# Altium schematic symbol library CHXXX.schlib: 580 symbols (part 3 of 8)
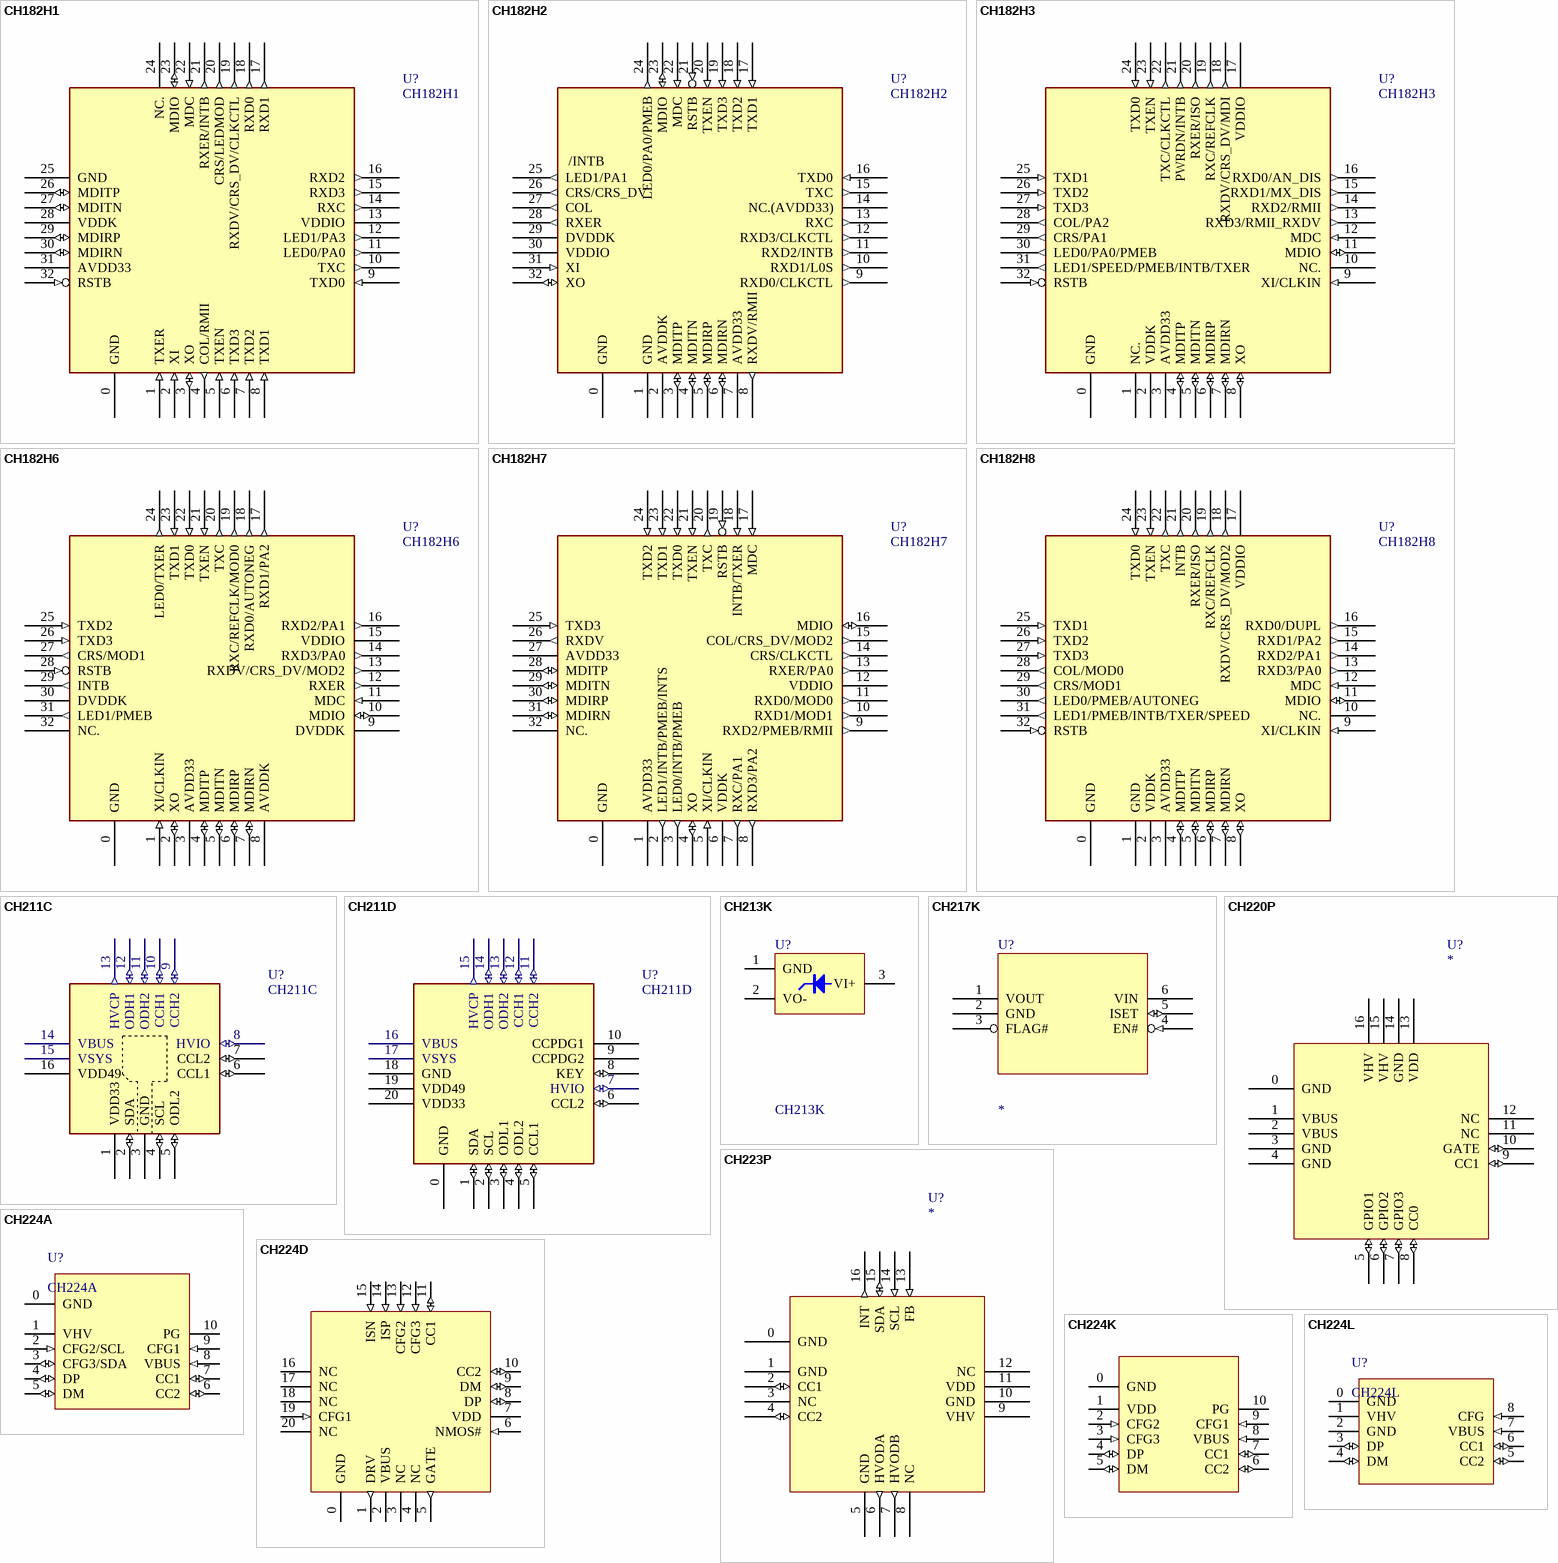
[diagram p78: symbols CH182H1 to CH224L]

## CH182H6
designator U?
MII/RMII 10/100M Ethernet PHY (Transceiver) with auto MDIX
footprint QFN32_5X5
pins: 0 GND (power), 1 XI/CLKIN (in), 2 XO (io), 3 AVDD33 (power), 4 MDITP (io), 5 MDITN (io), 6 MDIRP (io), 7 MDIRN (io), 8 AVDDK (power), 9 DVDDK (power), 10 MDIO (io), 11 MDC (in), 12 RXER (out), 13 RXDV/CRS_DV/MOD2 (out), 14 RXD3/PA0 (out), 15 VDDIO (power), 16 RXD2/PA1 (out), 17 RXD1/PA2 (out), 18 RXD0/AUTONEG (out), 19 RXC/REFCLK/MOD0 (out), 20 TXC (out), 21 TXEN (in), 22 TXD0 (in), 23 TXD1 (in), 24 LED0/TXER (out), 25 TXD2 (in), 26 TXD3 (in), 27 CRS/MOD1 (out), 28 RSTB (in), 29 INTB (out), 30 DVDDK (power), 31 LED1/PMEB (out), 32 NC.

## CH182H7
designator U?
MII/RMII 10/100M Ethernet PHY (Transceiver) with auto MDIX
footprint QFN32_5X5
pins: 0 GND (power), 1 AVDD33 (power), 2 LED1/INTB/PMEB/INTS (out), 3 LED0/INTB/PMEB (out), 4 XO (io), 5 XI/CLKIN (in), 6 VDDK (power), 7 RXC/PA1 (out), 8 RXD3/PA2 (out), 9 RXD2/PMEB/RMII (out), 10 RXD1/MOD1 (out), 11 RXD0/MOD0 (out), 12 VDDIO (power), 13 RXER/PA0 (out), 14 CRS/CLKCTL (out), 15 COL/CRS_DV/MOD2 (out), 16 MDIO (io), 17 MDC (in), 18 INTB/TXER (in), 19 RSTB (in), 20 TXC (out), 21 TXEN (in), 22 TXD0 (in), 23 TXD1 (in), 24 TXD2 (in), 25 TXD3 (in), 26 RXDV (out), 27 AVDD33 (power), 28 MDITP (io), 29 MDITN (io), 30 MDIRP (io), 31 MDIRN (io), 32 NC.

## CH182H8
designator U?
MII/RMII 10/100M Ethernet PHY (Transceiver) with auto MDIX
footprint QFN32_5X5
pins: 0 GND (power), 1 GND (power), 2 VDDK (power), 3 AVDD33 (power), 4 MDITP (io), 5 MDITN (io), 6 MDIRP (io), 7 MDIRN (io), 8 XO (io), 9 XI/CLKIN (in), 10 NC., 11 MDIO (io), 12 MDC (in), 13 RXD3/PA0 (out), 14 RXD2/PA1 (out), 15 RXD1/PA2 (out), 16 RXD0/DUPL (out), 17 VDDIO (power), 18 RXDV/CRS_DV/MOD2 (out), 19 RXC/REFCLK (out), 20 RXER/ISO (out), 21 INTB (out), 22 TXC (out), 23 TXEN (in), 24 TXD0 (in), 25 TXD1 (in), 26 TXD2 (in), 27 TXD3 (in), 28 COL/MOD0 (out), 29 CRS/MOD1 (out), 30 LED0/PMEB/AUTONEG (out), 31 LED1/PMEB/INTB/TXER/SPEED (out), 32 RSTB (in)

## CH211C
designator U?
28V USB PD & Type-C high voltage interface
footprint QFN16C_2X2
pins: 1 VDD33 (power), 2 SDA (io), 3 GND (power), 4 SCL (io), 5 ODL2 (io), 6 CCL1 (io), 7 CCL2 (io), 8 HVIO (io), 9 CCH2 (io), 10 CCH1 (io), 11 ODH2 (io), 12 ODH1 (io), 13 HVCP (out), 14 VBUS (power), 15 VSYS (power), 16 VDD49 (power)

## CH211D
designator U?
28V USB PD & Type-C high voltage interface
footprint QFN20_3X3
pins: 0 GND (power), 1 SDA (io), 2 SCL (io), 3 ODL1 (io), 4 ODL2 (io), 5 CCL1 (io), 6 CCL2 (io), 7 HVIO (io), 8 KEY (io), 9 CCPDG2 (power), 10 CCPDG1 (power), 11 CCH2 (io), 12 CCH1 (io), 13 ODH2 (io), 14 ODH1 (io), 15 HVCP (out), 16 VBUS (power), 17 VSYS (power), 18 GND (power), 19 VDD49 (power), 20 VDD33 (power)

## CH213K
designator U?
Ideal Diode 5V*1A
footprint SOT23L (Footprint not found)
footprint SOT-23-3
pins: 1 GND (power), 2 VO- (power), 3 VI+ (power)

## CH217K
designator U?
Current-Limited USB Power Distribution Switch
footprint SOT-23-6
pins: 1 VOUT (power), 2 GND (power), 3 FLAG# (oc), 4 EN# (in), 5 ISET (io), 6 VIN (power)

## CH220P
designator U?
USB PD & Type-C Power Manager
footprint QFN16_3X3
pins: 0 GND (power), 1 VBUS (power), 2 VBUS (power), 3 GND (power), 4 GND (power), 5 GPIO1 (io), 6 GPIO2 (io), 7 GPIO3 (io), 8 CC0 (io), 9 CC1 (io), 10 GATE (io), 11 NC, 12 NC, 13 VDD (power), 14 GND (power), 15 VHV (power), 16 VHV (power)

## CH223P
designator U?
USB PD & Type-C Power Provider Controller
footprint QFN16_3X3
pins: 0 GND (power), 1 GND, 2 CC1 (io), 3 NC (power), 4 CC2 (io), 5 GND (power), 6 HVODA (out), 7 HVODB (out), 8 NC, 9 VHV (power), 10 GND (power), 11 VDD (power), 12 NC, 13 FB (in), 14 SCL (in), 15 SDA (io), 16 INT (out)

## CH224A
designator U?
USB PD & Type-C & Fast Charge Power Consumer Controller
footprint ESSOP10
pins: 0 GND (power), 1 VHV (power), 2 CFG2/SCL (in), 3 CFG3/SDA (io), 4 DP (io), 5 DM (io), 6 CC2 (io), 7 CC1 (io), 8 VBUS (in), 9 CFG1 (in), 10 PG

## CH224D
designator U?  (value not drawn)
USB PD & Type-C & Fast Charge Power Consumer Controller
footprint QFN20_3X3
pins: 0 GND (power), 1 DRV (out), 2 VBUS (power), 3 NC, 4 NC, 5 GATE (out), 6 NMOS# (in), 7 VDD (power), 8 DP (io), 9 DM (io), 10 CC2 (io), 11 CC1 (io), 12 CFG3 (in), 13 CFG2 (in), 14 ISP (in), 15 ISN (in), 16 NC, 17 NC, 18 NC, 19 CFG1 (in), 20 NC

## CH224K
designator U?  (value not drawn)
USB PD & Type-C & Fast Charge Power Consumer Controller
footprint ESSOP10
pins: 0 GND (power), 1 VDD (power), 2 CFG2 (in), 3 CFG3 (in), 4 DP (io), 5 DM (io), 6 CC2 (io), 7 CC1 (io), 8 VBUS (in), 9 CFG1 (in), 10 PG

## CH224L
designator U?
USB PD & Type-C & Fast Charge Power Consumer Controller
footprint DFN8_2x2
pins: 0 GND (power), 1 VHV (power), 2 GND (power), 3 DP (io), 4 DM (io), 5 CC2 (io), 6 CC1 (io), 7 VBUS (in), 8 CFG (in)

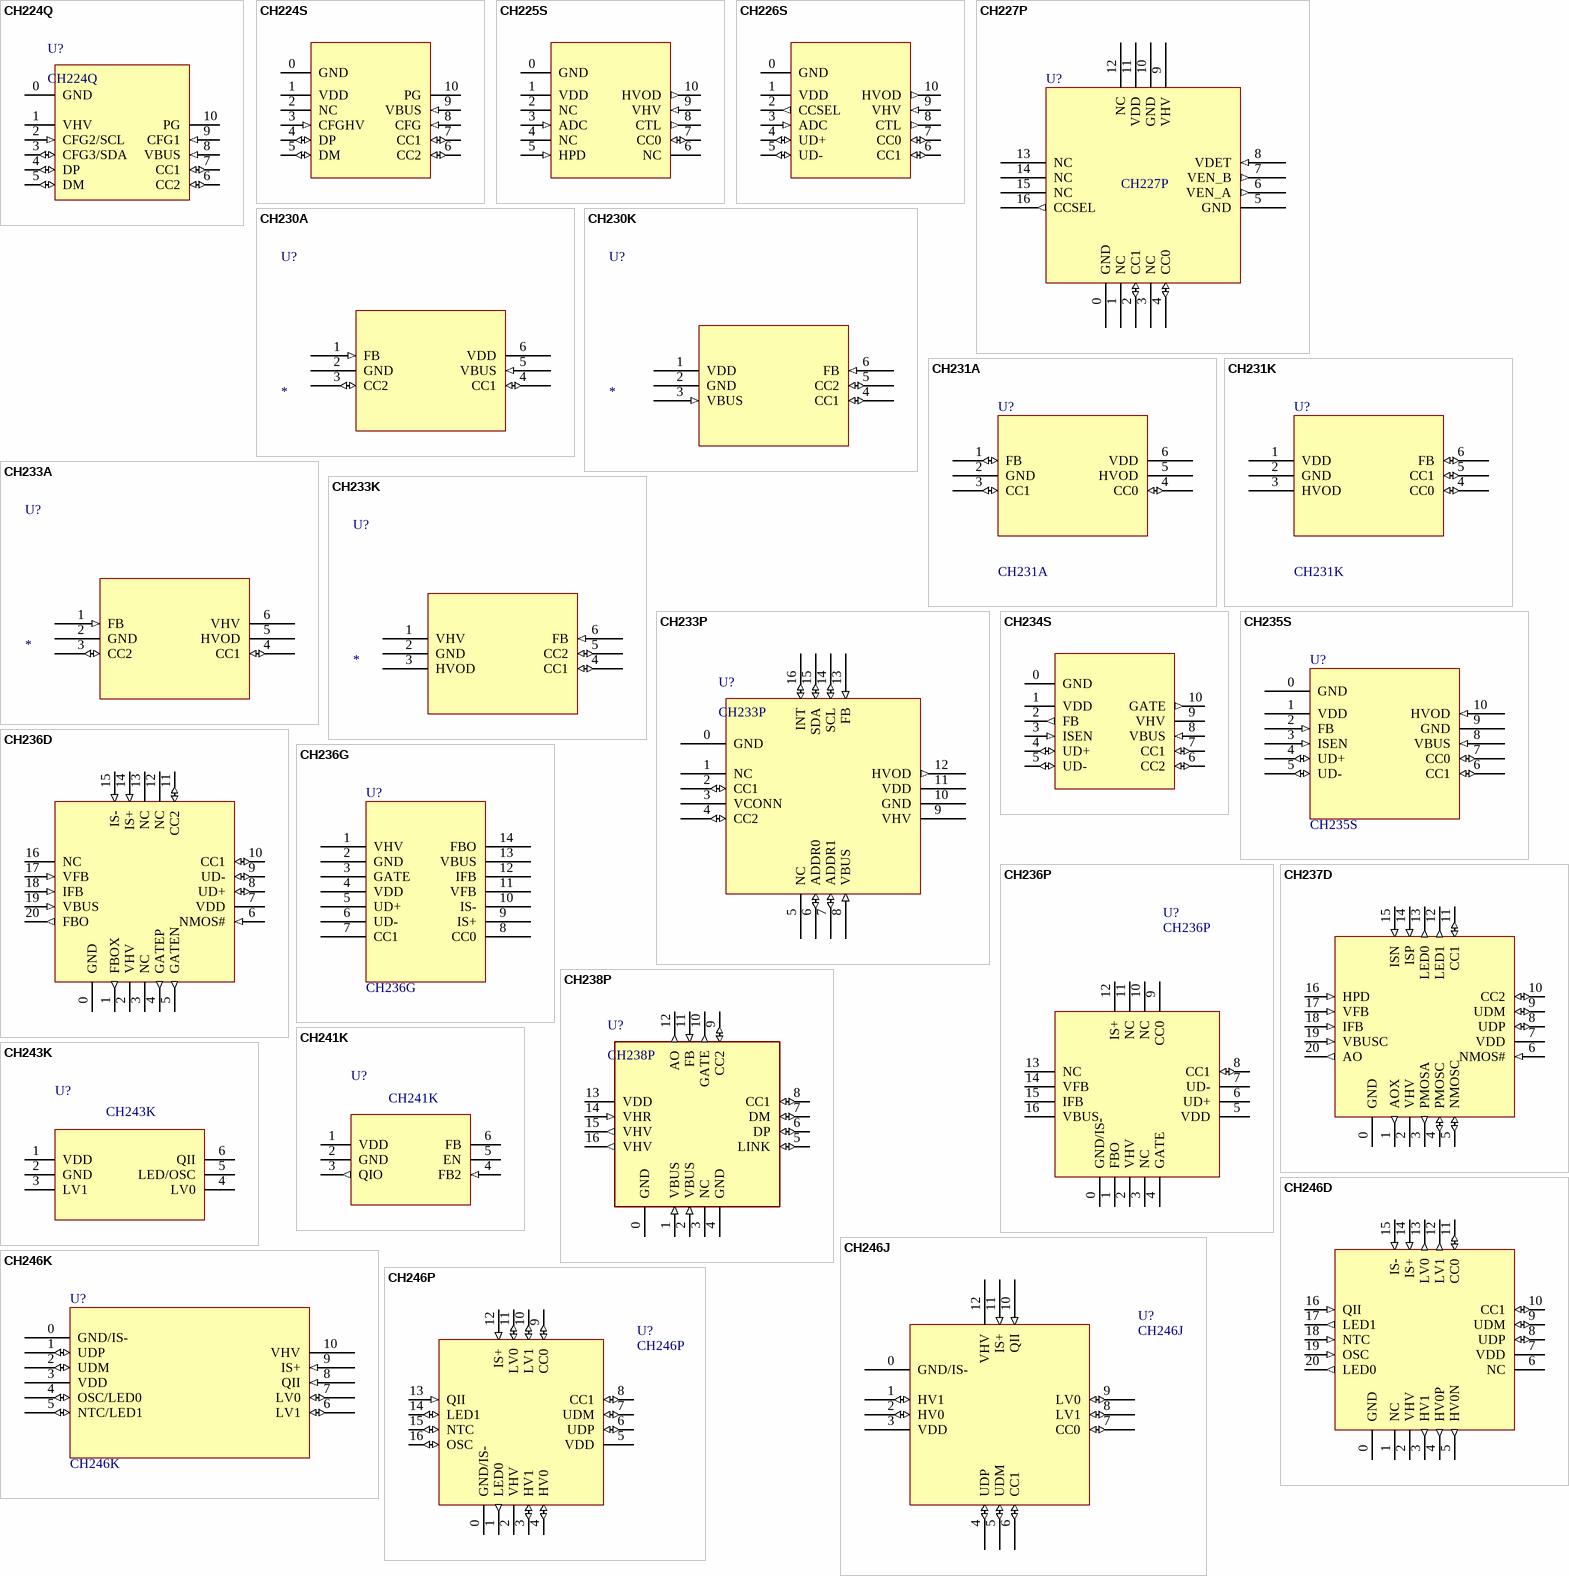
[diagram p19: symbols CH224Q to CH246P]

## CH224Q
designator U?
USB PD & Type-C & Fast Charge Power Consumer Controller
footprint DFN10_2X2 (Footprint not found)
pins: 0 GND (power), 1 VHV (power), 2 CFG2/SCL (in), 3 CFG3/SDA (io), 4 DP (io), 5 DM (io), 6 CC2 (io), 7 CC1 (io), 8 VBUS (in), 9 CFG1 (in), 10 PG

## CH224S
designator U?  (value not drawn)
USB PD & Type-C & Fast Charge Power Consumer Controller
footprint ESSOP10
pins: 0 GND (power), 1 VDD (power), 2 NC, 3 CFGHV (in), 4 DP (io), 5 DM (io), 6 CC2 (io), 7 CC1 (io), 8 CFG (in), 9 VBUS (in), 10 PG

## CH225S
designator U?  (value not drawn)
USB PD & Type-C & Fast Charge Power Consumer Controller
footprint ESSOP10
pins: 0 GND (power), 1 VDD (power), 2 NC, 3 ADC (in), 4 NC, 5 HPD (in), 6 NC, 7 CC0 (io), 8 CTL (out), 9 VHV (in), 10 HVOD (out)

## CH226S
designator U?  (value not drawn)
USB PD & Type-C & Fast Charge Power Consumer Controller
footprint ESSOP10
pins: 0 GND (power), 1 VDD (power), 2 CCSEL (out), 3 ADC (in), 4 UD+ (io), 5 UD- (io), 6 CC1 (io), 7 CC0 (io), 8 CTL (out), 9 VHV (in), 10 HVOD (out)

## CH227P
designator U?
USB PD & Type-C & Fast Charge Power Consumer Controller
footprint QFN16_3X3
pins: 0 GND (power), 1 NC, 2 CC1 (io), 3 NC, 4 CC0 (io), 5 GND (power), 6 VEN_A (out), 7 VEN_B (out), 8 VDET (in), 9 VHV (power), 10 GND (power), 11 VDD (power), 12 NC, 13 NC, 14 NC, 15 NC, 16 CCSEL (out)

## CH230A
designator U?
USB PD & Type-C Power Provider Controller
footprint SOT-23-6
pins: 1 FB (in), 2 GND (power), 3 CC2 (io), 4 CC1 (io), 5 VBUS (in), 6 VDD (power)

## CH230K
designator U?
USB PD & Type-C Power Provider Controller
footprint SOT-23-6
pins: 1 VDD (power), 2 GND (power), 3 VBUS (in), 4 CC1 (io), 5 CC2 (io), 6 FB (in)

## CH231A
designator U?
USB PD & Type-C Power Provider Controller
footprint SOT-23-6
pins: 1 FB (io), 2 GND (power), 3 CC1 (io), 4 CC0 (io), 5 HVOD (oc), 6 VDD (power)

## CH231K
designator U?
USB PD & Type-C Power Provider Controller
footprint SOT-23-6
pins: 1 VDD (power), 2 GND (power), 3 HVOD (oc), 4 CC0 (io), 5 CC1 (io), 6 FB (io)

## CH233A
designator U?
USB PD & Type-C Power Provider Controller
footprint SOT-23-6
pins: 1 FB (in), 2 GND (power), 3 CC2 (io), 4 CC1 (io), 5 HVOD (oc), 6 VHV (power)

## CH233K
designator U?
USB PD & Type-C Power Provider Controller
footprint SOT-23-6
pins: 1 VHV (power), 2 GND (power), 3 HVOD (oc), 4 CC1 (io), 5 CC2 (io), 6 FB (in)

## CH233P
designator U?
USB PD & Type-C Power Provider Controller
footprint QFN16_3X3
pins: 0 GND (power), 1 NC, 2 CC1 (io), 3 VCONN (power), 4 CC2 (io), 5 NC, 6 ADDR0 (io), 7 ADDR1 (io), 8 VBUS (in), 9 VHV (power), 10 GND (power), 11 VDD (power), 12 HVOD (out), 13 FB (in), 14 SCL (io), 15 SDA (io), 16 INT (io)

## CH234S
designator U?  (value not drawn)
USB PD & Type-C & Fast Charge Power Provider Controller
footprint ESSOP10
pins: 0 GND (power), 1 VDD (power), 2 FB (out), 3 ISEN (in), 4 UD+ (io), 5 UD- (io), 6 CC2 (io), 7 CC1 (io), 8 VBUS (in), 9 VHV (power), 10 GATE (out)

## CH235S
designator U?
USB PD & Type-C & Fast Charge Power Provider Controller
footprint ESSOP10
pins: 0 GND (power), 1 VDD (power), 2 FB (in), 3 ISEN (in), 4 UD+ (io), 5 UD- (io), 6 CC1 (io), 7 CC0 (io), 8 VBUS (in), 9 GND (power), 10 HVOD (in)

## CH236D
designator U?  (value not drawn)
USB PD & Type-C & Fast Charge Power Provider Controller
footprint QFN20_3X3
pins: 0 GND (power), 1 FBOX (out), 2 VHV (power), 3 NC, 4 GATEP (out), 5 GATEN (out), 6 NMOS# (in), 7 VDD (power), 8 UD+ (io), 9 UD- (io), 10 CC1 (io), 11 CC2 (io), 12 NC, 13 NC, 14 IS+ (in), 15 IS- (in), 16 NC, 17 VFB (in), 18 IFB (in), 19 VBUS (in), 20 FBO (out)

## CH236G
designator U?
USB PD & Type-C & Fast Charge Power Provider Controller
footprint SOP14
pins: 1 VHV, 2 GND (power), 3 GATE, 4 VDD (power), 5 UD+, 6 UD-, 7 CC1, 8 CC0 (power), 9 IS+, 10 IS- (power), 11 VFB, 12 IFB, 13 VBUS, 14 FBO (power)

## CH236P
designator U?
USB PD & Type-C & Fast Charge Power Provider Controller
footprint QFN16_3X3
pins: 0 GND/IS- (power), 1 FBO, 2 VHV (power), 3 NC, 4 GATE, 5 VDD (power), 6 UD+, 7 UD-, 8 CC1 (io), 9 CC0, 10 NC, 11 NC, 12 IS+, 13 NC, 14 VFB, 15 IFB, 16 VBUS

## CH237D
designator U?  (value not drawn)
USB PD & Type-C & Fast Charge Power Provider Controller, A+C
footprint QFN20_3X3
pins: 0 GND (power), 1 AOX (out), 2 VHV (power), 3 PMOSA (out), 4 PMOSC (io), 5 NMOSC (io), 6 NMOS# (in), 7 VDD (power), 8 UDP (io), 9 UDM (io), 10 CC2 (io), 11 CC1 (io), 12 LED1 (out), 13 LED0 (out), 14 ISP (in), 15 ISN (in), 16 HPD (in), 17 VFB (in), 18 IFB (in), 19 VBUSC (in), 20 AO (out)

## CH238P
designator U?
USB PD & Type-C & Fast Charge Power Provider Controller
footprint QFN16_3X3
pins: 0 GND, 1 VBUS (in), 2 VBUS (in), 3 NC, 4 GND, 5 LINK (io), 6 DP (io), 7 DM (io), 8 CC1 (io), 9 CC2 (io), 10 GATE (out), 11 FB (in), 12 AO (out), 13 VDD, 14 VHR (in), 15 VHV (out), 16 VHV (out)

## CH241K
designator U?
5W wireless power receiver IC
footprint SOT-23-6
pins: 1 VDD (power), 2 GND (power), 3 QIO (out), 4 FB2 (in), 5 EN (power), 6 FB

## CH243K
designator U?
5W wireless power transmitter IC
footprint SOT-23-6
pins: 1 VDD (power), 2 GND (power), 3 LV1, 4 LV0, 5 LED/OSC (power), 6 QII

## CH246D
designator U?  (value not drawn)
Wireless Charge Power Provider Controller with USB PD & Fast Charge Sink
footprint QFN20_3X3
pins: 0 GND (power), 1 NC, 2 VHV (power), 3 HV1 (out), 4 HV0P (out), 5 HV0N (out), 6 NC, 7 VDD (power), 8 UDP (io), 9 UDM (io), 10 CC1 (io), 11 CC0 (io), 12 LV1 (out), 13 LV0 (out), 14 IS+ (in), 15 IS- (in), 16 QII (in), 17 LED1 (out), 18 NTC (in), 19 OSC (in), 20 LED0 (out)

## CH246J
designator U?
Wireless Charge Power Provider Controller with USB PD & Fast Charge Sink
footprint QFN12_2X2
pins: 0 GND/IS- (power), 1 HV1 (io), 2 HV0 (io), 3 VDD (power), 4 UDP (io), 5 UDM (io), 6 CC1 (io), 7 CC0 (io), 8 LV1 (io), 9 LV0 (io), 10 QII (in), 11 IS+ (in), 12 VHV (power)

## CH246K
designator U?
Wireless Charge Power with X-drive
footprint ESSOP10
pins: 0 GND/IS- (power), 1 UDP (io), 2 UDM (io), 3 VDD (power), 4 OSC/LED0 (io), 5 NTC/LED1 (io), 6 LV1 (io), 7 LV0 (io), 8 QII (in), 9 IS+ (in), 10 VHV (power)

## CH246P
designator U?
Wireless Charge Power Provider Controller with USB PD & Fast Charge Sink
footprint QFN16_3X3
pins: 0 GND/IS- (power), 1 LED0 (out), 2 VHV (power), 3 HV1 (io), 4 HV0 (io), 5 VDD (power), 6 UDP (io), 7 UDM (io), 8 CC1 (io), 9 CC0 (io), 10 LV1 (io), 11 LV0 (io), 12 IS+ (in), 13 QII (in), 14 LED1 (io), 15 NTC (io), 16 OSC (io)

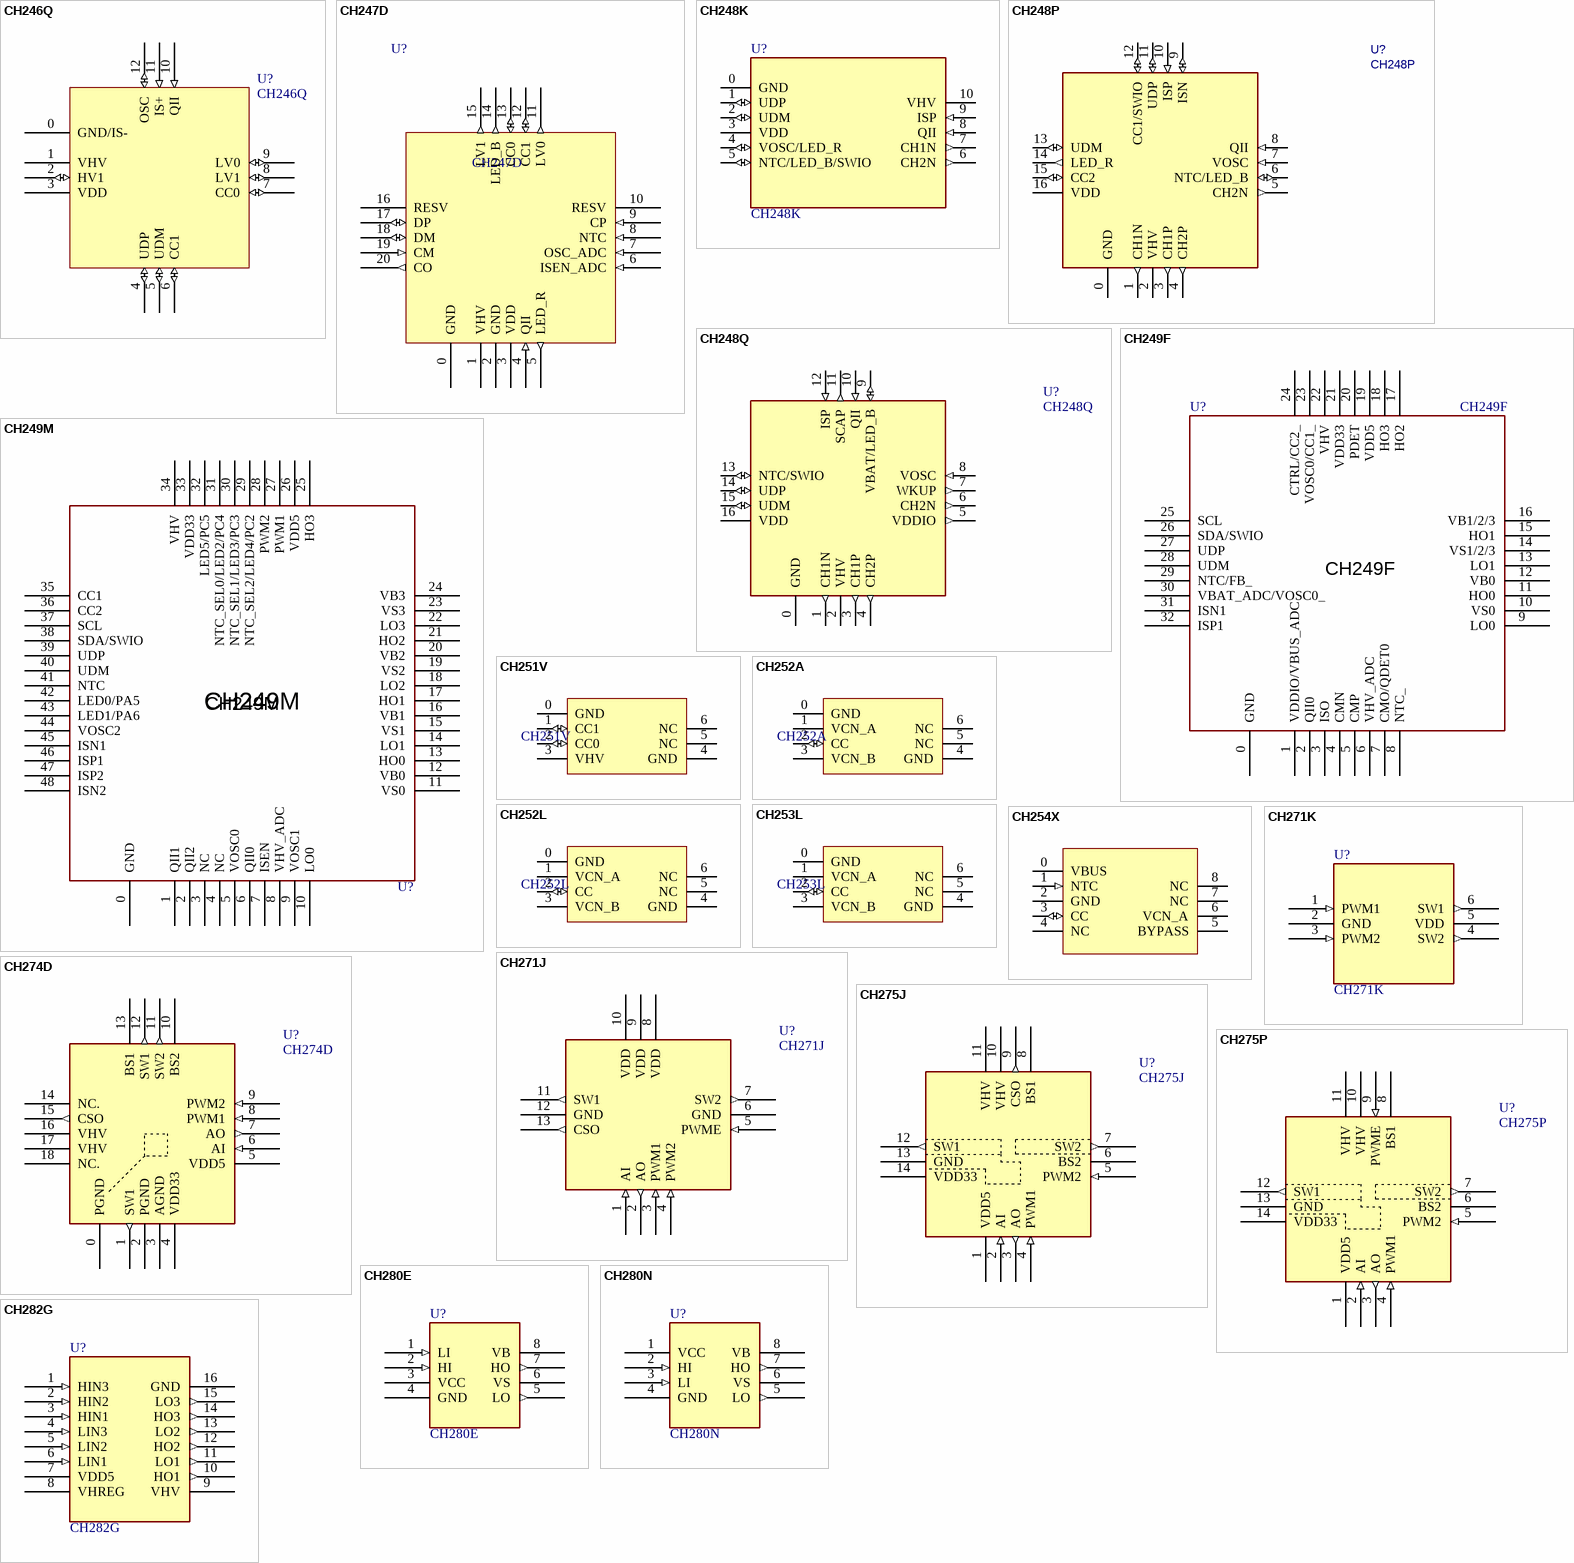
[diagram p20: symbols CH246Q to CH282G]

## CH246Q
designator U?
Wireless Charge Power with X-drive & PD Charge
footprint QFN12_2X2
pins: 0 GND/IS- (power), 1 VHV (power), 2 HV1 (io), 3 VDD (power), 4 UDP (io), 5 UDM (io), 6 CC1 (io), 7 CC0 (io), 8 LV1 (io), 9 LV0 (io), 10 QII (in), 11 IS+ (in), 12 OSC (io)

## CH247D
designator U?
Wireless Charge Power Provider Controller with USB PD & Fast Charge Sink
footprint QFN20_3X3
pins: 0 GND (power), 1 VHV (power), 2 GND (power), 3 VDD (power), 4 QII (in), 5 LED_R (out), 6 ISEN_ADC (in), 7 OSC_ADC (in), 8 NTC (in), 9 CP (in), 10 RESV, 11 LV0 (out), 12 CC1 (io), 13 CC0 (io), 14 LED_B (out), 15 LV1 (out), 16 RESV, 17 DP (io), 18 DM (io), 19 CM (in), 20 CO (out)

## CH248K
designator U?
RISC-V MCU with PD/ADC/UART/OA, for wireless charging
footprint ESSOP10
pins: 0 GND (power), 1 UDP (io), 2 UDM (io), 3 VDD (power), 4 VOSC/LED_R (io), 5 NTC/LED_B/SWIO (io), 6 CH2N (out), 7 CH1N (out), 8 QII (in), 9 ISP (in), 10 VHV (power)

## CH248P
designator U?
RISC-V MCU with PD/ADC/UART/OA, for wireless charging
footprint QFN16_3X3
pins: 0 GND (power), 1 CH1N (out), 2 VHV (power), 3 CH1P (out), 4 CH2P (out), 5 CH2N (out), 6 NTC/LED_B (io), 7 VOSC (in), 8 QII (in), 9 ISN (io), 10 ISP (in), 11 UDP (io), 12 CC1/SWIO (io), 13 UDM (io), 14 LED_R (out), 15 CC2 (io), 16 VDD (power)

## CH248Q
designator U?
RISC-V MCU with ADC/UART/OA
footprint QFN16_3X3
pins: 0 GND (power), 1 CH1N (out), 2 VHV (power), 3 CH1P (out), 4 CH2P (out), 5 VDDIO (out), 6 CH2N (out), 7 WKUP (out), 8 VOSC (in), 9 VBAT/LED_B (io), 10 QII (in), 11 SCAP (out), 12 ISP (in), 13 NTC/SWIO (io), 14 UDP (io), 15 UDM (io), 16 VDD (power)

## CH249F
designator U?
Wireless charging transmitter, supporting MPP, EPP, BPP, earphones, smartwatches, and other devices.
footprint QFN32_4X4
pins: 0 GND (power), 1 VDDIO/VBUS_ADC, 2 QII0, 3 ISO, 4 CMN, 5 CMP, 6 VHV_ADC, 7 CMO/QDET0, 8 NTC_, 9 LO0, 10 VS0, 11 HO0, 12 VB0, 13 LO1, 14 VS1/2/3, 15 HO1, 16 VB1/2/3, 17 HO2, 18 HO3, 19 VDD5 (power), 20 PDET, 21 VDD33 (power), 22 VHV (power), 23 VOSC0/CC1_, 24 CTRL/CC2_, 25 SCL, 26 SDA/SWIO, 27 UDP, 28 UDM, 29 NTC/FB_, 30 VBAT_ADC/VOSC0_, 31 ISN1, 32 ISP1

## CH249M
designator U?
Wireless charging transmitter, supporting EPP, BPP, earphones, smartwatches, and other devices£¬supporting three-way simultaneous charging.
footprint QFN48_5X5
pins: 0 GND (power), 1 QII1 (hiz), 2 QII2, 3 NC (hiz), 4 NC (hiz), 5 VOSC0 (hiz), 6 QII0 (hiz), 7 ISEN (hiz), 8 VHV_ADC (hiz), 9 VOSC1 (hiz), 10 LO0 (hiz), 11 VS0 (hiz), 12 VB0 (hiz), 13 HO0 (hiz), 14 LO1 (hiz), 15 VS1 (hiz), 16 VB1 (hiz), 17 HO1 (hiz), 18 LO2 (hiz), 19 VS2, 20 VB2 (hiz), 21 HO2 (hiz), 22 LO3 (hiz), 23 VS3 (hiz), 24 VB3 (hiz), 25 HO3 (hiz), 26 VDD5 (power), 27 PWM1 (hiz), 28 PWM2 (hiz), 29 NTC_SEL2/LED4/PC2 (hiz), 30 NTC_SEL1/LED3/PC3 (hiz), 31 NTC_SEL0/LED2/PC4 (hiz), 32 LED5/PC5 (oc), 33 VDD33 (hiz), 34 VHV (power), 35 CC1 (hiz), 36 CC2 (hiz), 37 SCL, 38 SDA/SWIO (hiz), 39 UDP, 40 UDM, 41 NTC, 42 LED0/PA5 (hiz), 43 LED1/PA6, 44 VOSC2, 45 ISN1 (hiz), 46 ISP1 (hiz), 47 ISP2 (hiz), 48 ISN2 (hiz)

## CH251V
designator U?
USB Type-C cable E-Marker
footprint DFN6_2X2
pins: 0 GND (power), 1 CC1 (io), 2 CC0 (io), 3 VHV (power), 4 GND (power), 5 NC, 6 NC

## CH252A
designator U?
USB Type-C cable E-Marker
footprint DFN6_2X2
pins: 0 GND (power), 1 VCN_A (power), 2 CC (io), 3 VCN_B (power), 4 GND (power), 5 NC, 6 NC

## CH252L
designator U?
USB Type-C cable E-Marker
footprint DFN6_2X2
pins: 0 GND (power), 1 VCN_A (power), 2 CC (io), 3 VCN_B (power), 4 GND (power), 5 NC, 6 NC

## CH253L
designator U?
USB Type-C cable E-Marker
footprint DFN6_2X2
pins: 0 GND (power), 1 VCN_A (power), 2 CC (io), 3 VCN_B (power), 4 GND (power), 5 NC, 6 NC

## CH254X
designator U?  (value not drawn)
USB Type-C cable E-Marker with over temperature protection
footprint DFN8_2x2 (Footprint not found)
pins: 0 VBUS (power), 1 NTC (in), 2 GND (power), 3 CC (io), 4 NC, 5 BYPASS (power), 6 VCN_A (power), 7 NC, 8 NC

## CH271J
designator U?
5V Full-Bridge Power Stage for Wireless Power Transmitter
footprint QFN13F_2X2 (Footprint not found)
pins: 1 AI (in), 2 AO (out), 3 PWM1 (in), 4 PWM2 (in), 5 PWME (in), 6 GND (power), 7 SW2 (out), 8 VDD (power), 9 VDD (power), 10 VDD (power), 11 SW1 (out), 12 GND (power), 13 CSO (out)

## CH271K
designator U?
5V Full-Bridge Power Stage
footprint SOT-23-6
pins: 1 PWM1 (in), 2 GND (power), 3 PWM2 (in), 4 SW2 (out), 5 VDD (power), 6 SW1 (out)

## CH274D
designator U?
12V Full-Bridge Power Stage for Wireless Power Transmitter
footprint QFN18E_3X3
pins: 0 PGND (power), 1 SW1 (out), 2 PGND (power), 3 AGND (power), 4 VDD33 (power), 5 VDD5 (power), 6 AI (in), 7 AO (out), 8 PWM1 (in), 9 PWM2 (in), 10 BS2 (power), 11 SW2 (out), 12 SW1 (out), 13 BS1 (power), 14 NC., 15 CSO (out), 16 VHV (power), 17 VHV (power), 18 NC.

## CH275J
designator U?
20V Full-Bridge Power Stage for Wireless Power Transmitter
footprint QFN14F_3X3 (Footprint not found)
pins: 1 VDD5 (power), 2 AI (in), 3 AO (out), 4 PWM1 (in), 5 PWM2 (in), 6 BS2 (power), 7 SW2 (out), 8 BS1 (power), 9 CSO (out), 10 VHV (power), 11 VHV (power), 12 SW1 (out), 13 GND (power), 14 VDD33 (power)

## CH275P
designator U?
20V Full-Bridge Power Stage for Wireless Power Transmitter
footprint QFN14F_3X3 (Footprint not found)
pins: 1 VDD5 (power), 2 AI (in), 3 AO (out), 4 PWM1 (in), 5 PWM2 (in), 6 BS2 (power), 7 SW2 (out), 8 BS1 (power), 9 PWME (in), 10 VHV (power), 11 VHV (power), 12 SW1 (out), 13 GND (power), 14 VDD33 (power)

## CH280E
designator U?
NMOS half-bridge gate driver
footprint SOP8
pins: 1 LI (in), 2 HI (in), 3 VCC (power), 4 GND (power), 5 LO (out), 6 VS (power), 7 HO (out), 8 VB (power)

## CH280N
designator U?
NMOS half-bridge gate driver
footprint SOP8
pins: 1 VCC (power), 2 HI (in), 3 LI (in), 4 GND (power), 5 LO (out), 6 VS (power), 7 HO (out), 8 VB (power)

## CH282G
designator U?
three-phase P/NMOS gate driver with LDO
footprint SOP16
pins: 1 HIN3 (in), 2 HIN2 (in), 3 HIN1 (in), 4 LIN3 (in), 5 LIN2 (in), 6 LIN1 (in), 7 VDD5 (power), 8 VHREG (power), 9 VHV (power), 10 HO1 (out), 11 LO1 (out), 12 HO2 (out), 13 LO2 (out), 14 HO3 (out), 15 LO3 (out), 16 GND (power)

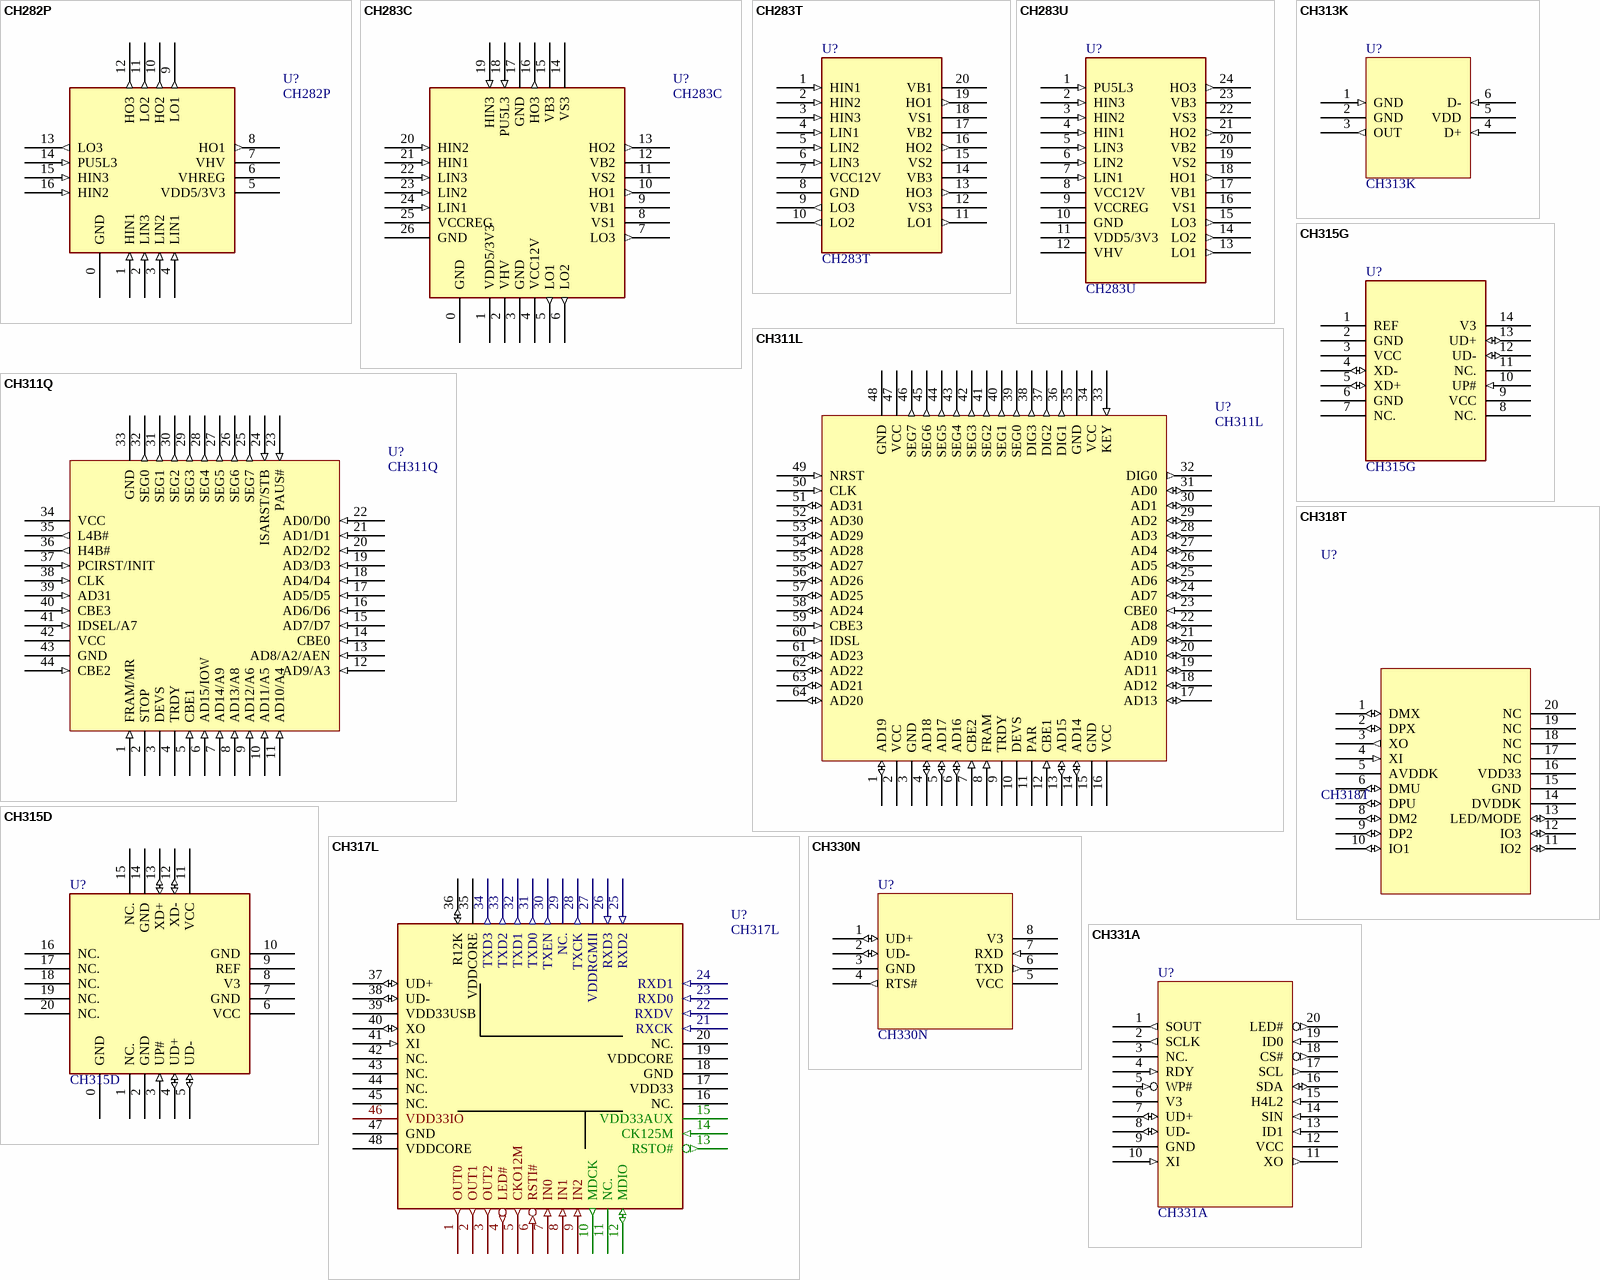
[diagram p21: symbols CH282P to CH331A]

## CH282P
designator U?
three-phase P/NMOS gate driver with LDO
footprint QFN16_3X3
pins: 0 GND (power), 1 HIN1 (in), 2 LIN3 (in), 3 LIN2 (in), 4 LIN1 (in), 5 VDD5/3V3 (power), 6 VHREG (power), 7 VHV (power), 8 HO1 (out), 9 LO1 (out), 10 HO2 (out), 11 LO2 (out), 12 HO3 (out), 13 LO3 (out), 14 PU5L3 (in), 15 HIN3 (in), 16 HIN2 (in)

## CH283C
designator U?
three-phase NMOS gate driver with LDO
footprint QFN26C_3X3
pins: 0 GND (power), 1 VDD5/3V3 (power), 2 VHV (power), 3 GND (power), 4 VCC12V (power), 5 LO1 (out), 6 LO2 (out), 7 LO3 (out), 8 VS1 (power), 9 VB1 (power), 10 HO1 (out), 11 VS2 (power), 12 VB2 (power), 13 HO2 (out), 14 VS3 (power), 15 VB3 (power), 16 HO3 (out), 17 GND (power), 18 PU5L3 (in), 19 HIN3 (in), 20 HIN2 (in), 21 HIN1 (in), 22 LIN3 (in), 23 LIN2 (in), 24 LIN1 (in), 25 VCCREG (power), 26 GND (power)

## CH283T
designator U?
three-phase NMOS gate driver
footprint TSSOP20
pins: 1 HIN1 (in), 2 HIN2 (in), 3 HIN3 (in), 4 LIN1 (in), 5 LIN2 (in), 6 LIN3 (in), 7 VCC12V (power), 8 GND (power), 9 LO3 (out), 10 LO2 (out), 11 LO1 (out), 12 VS3 (power), 13 HO3 (out), 14 VB3 (power), 15 VS2 (power), 16 HO2 (out), 17 VB2 (power), 18 VS1 (power), 19 HO1 (out), 20 VB1 (power)

## CH283U
designator U?
three-phase NMOS gate driver with LDO
footprint QSOP24
pins: 1 PU5L3 (in), 2 HIN3 (in), 3 HIN2 (in), 4 HIN1 (in), 5 LIN3 (in), 6 LIN2 (in), 7 LIN1 (in), 8 VCC12V (power), 9 VCCREG (power), 10 GND (power), 11 VDD5/3V3 (power), 12 VHV (power), 13 LO1 (out), 14 LO2 (out), 15 LO3 (out), 16 VS1 (power), 17 VB1 (power), 18 HO1 (out), 19 VS2 (power), 20 VB2 (power), 21 HO2 (out), 22 VS3 (power), 23 VB3 (power), 24 HO3 (out)

## CH311L
designator U?
PC debug port monitor, 4 Digits * 8 Segments, PCI
footprint LQFP64
pins: 1 AD19 (io), 2 VCC (power), 3 GND (power), 4 AD18 (io), 5 AD17 (io), 6 AD16 (io), 7 CBE2 (in), 8 FRAM (in), 9 TRDY (hiz), 10 DEVS (hiz), 11 PAR (hiz), 12 CBE1 (in), 13 AD15 (io), 14 AD14 (io), 15 GND (power), 16 VCC (power), 17 AD13 (io), 18 AD12 (io), 19 AD11 (io), 20 AD10 (io), 21 AD9 (io), 22 AD8 (io), 23 CBE0 (in), 24 AD7 (io), 25 AD6 (io), 26 AD5 (io), 27 AD4 (io), 28 AD3 (io), 29 AD2 (io), 30 AD1 (io), 31 AD0 (io), 32 DIG0 (out), 33 KEY (in), 34 VCC (power), 35 GND (power), 36 DIG1 (out), 37 DIG2 (out), 38 DIG3 (out), 39 SEG0 (out), 40 SEG1 (out), 41 SEG2 (out), 42 SEG3 (out), 43 SEG4 (out), 44 SEG5 (out), 45 SEG6 (out), 46 SEG7 (out), 47 VCC (power), 48 GND (power), 49 NRST (in), 50 CLK (in), 51 AD31 (io), 52 AD30 (io), 53 AD29 (io), 54 AD28 (io), 55 AD27 (io), 56 AD26 (io), 57 AD25 (io), 58 AD24 (io), 59 CBE3 (in), 60 IDSL (in), 61 AD23 (io), 62 AD22 (io), 63 AD21 (io), 64 AD20 (io)

## CH311Q
designator U?
PC debug port monitor, 2 Digits * 8 Segments, PCI & ISA & LPT
footprint LQFP44
pins: 1 FRAM/MR (in), 2 STOP (hiz), 3 DEVS (hiz), 4 TRDY (hiz), 5 CBE1 (in), 6 AD15/IOW (in), 7 AD14/A9 (in), 8 AD13/A8 (in), 9 AD12/A6 (in), 10 AD11/A5 (in), 11 AD10/A4 (in), 12 AD9/A3 (in), 13 AD8/A2/AEN (in), 14 CBE0 (in), 15 AD7/D7 (in), 16 AD6/D6 (in), 17 AD5/D5 (in), 18 AD4/D4 (in), 19 AD3/D3 (in), 20 AD2/D2 (in), 21 AD1/D1 (in), 22 AD0/D0 (in), 23 PAUS# (in), 24 ISARST/STB (in), 25 SEG7 (out), 26 SEG6 (out), 27 SEG5 (out), 28 SEG4 (out), 29 SEG3 (out), 30 SEG2 (out), 31 SEG1 (out), 32 SEG0 (out), 33 GND (power), 34 VCC (power), 35 L4B# (out), 36 H4B# (out), 37 PCIRST/INIT (in), 38 CLK (in), 39 AD31 (in), 40 CBE3 (in), 41 IDSEL/A7 (in), 42 VCC (power), 43 GND (power), 44 CBE2 (in)

## CH313K
designator U?
USB transfer detection
footprint SOT-363
pins: 1 GND (in), 2 GND (power), 3 OUT (out), 4 D+ (in), 5 VDD (power), 6 D- (in)

## CH315D
designator U?
USB lengthen wire controller, Full-Speed & Low-Speed
footprint QFN20_3X3 (Footprint not found)
pins: 0 GND (power), 1 NC., 2 GND (power), 3 UP# (in), 4 UD+ (io), 5 UD- (io), 6 VCC (power), 7 GND (power), 8 V3 (power), 9 REF (power), 10 GND (power), 11 VCC (power), 12 XD- (io), 13 XD+ (io), 14 GND (power), 15 NC., 16 NC., 17 NC., 18 NC., 19 NC., 20 NC.

## CH315G
designator U?
USB lengthen wire controller, Full-Speed & Low-Speed
footprint SOP14
pins: 1 REF (power), 2 GND (power), 3 VCC (power), 4 XD- (io), 5 XD+ (io), 6 GND (power), 7 NC., 8 NC., 9 VCC (power), 10 UP# (in), 11 NC., 12 UD- (io), 13 UD+ (io), 14 V3 (power)

## CH317L
designator U?
High-Speed USB lengthen wire controller for longer distance
footprint LQFP48
pins: 1 OUT0 (out), 2 OUT1 (out), 3 OUT2 (out), 4 LED# (out), 5 CKO12M (out), 6 RSTI# (in), 7 IN0 (in), 8 IN1 (in), 9 IN2 (in), 10 MDCK (out), 11 NC., 12 MDIO (io), 13 RSTO# (out), 14 CK125M (in), 15 VDD33AUX (power), 16 NC., 17 VDD33 (power), 18 GND (power), 19 VDDCORE (power), 20 NC., 21 RXCK (in), 22 RXDV (in), 23 RXD0 (in), 24 RXD1 (in), 25 RXD2 (in), 26 RXD3 (in), 27 VDDRGMII (power), 28 TXCK (out), 29 NC., 30 TXEN (out), 31 TXD0 (out), 32 TXD1 (out), 33 TXD2 (out), 34 TXD3 (out), 35 VDDCORE (power), 36 R12K (io), 37 UD+ (io), 38 UD- (io), 39 VDD33USB (power), 40 XO (io), 41 XI (in), 42 NC., 43 NC., 44 NC., 45 NC., 46 VDD33IO (power), 47 GND (power), 48 VDDCORE (power)

## CH318T
designator U?
2 ports High-Speed USB Hub Isolator
footprint TSSOP20
pins: 1 DMX (io), 2 DPX (io), 3 XO (out), 4 XI (in), 5 AVDDK (power), 6 DMU (io), 7 DPU (io), 8 DM2 (io), 9 DP2 (io), 10 IO1 (io), 11 IO2 (io), 12 IO3 (io), 13 LED/MODE (io), 14 DVDDK (power), 15 GND (power), 16 VDD33 (power), 17 NC, 18 NC, 19 NC, 20 NC

## CH330N
designator U?
USB to TTL Serial / UART
footprint SOP8
pins: 1 UD+ (io), 2 UD- (io), 3 GND (power), 4 RTS# (out), 5 VCC (power), 6 TXD (out), 7 RXD (in), 8 V3 (power)

## CH331A
designator U?
Mini USB Disk Controller for serial EEPROM or Flash
footprint SSOP20
pins: 1 SOUT (out), 2 SCLK (out), 3 NC., 4 RDY (in), 5 WP# (in), 6 V3 (power), 7 UD+ (io), 8 UD- (io), 9 GND (power), 10 XI (in), 11 XO (out), 12 VCC (power), 13 ID1 (in), 14 SIN (in), 15 H4L2 (in), 16 SDA (io), 17 SCL (out), 18 CS# (out), 19 ID0 (in), 20 LED# (out)

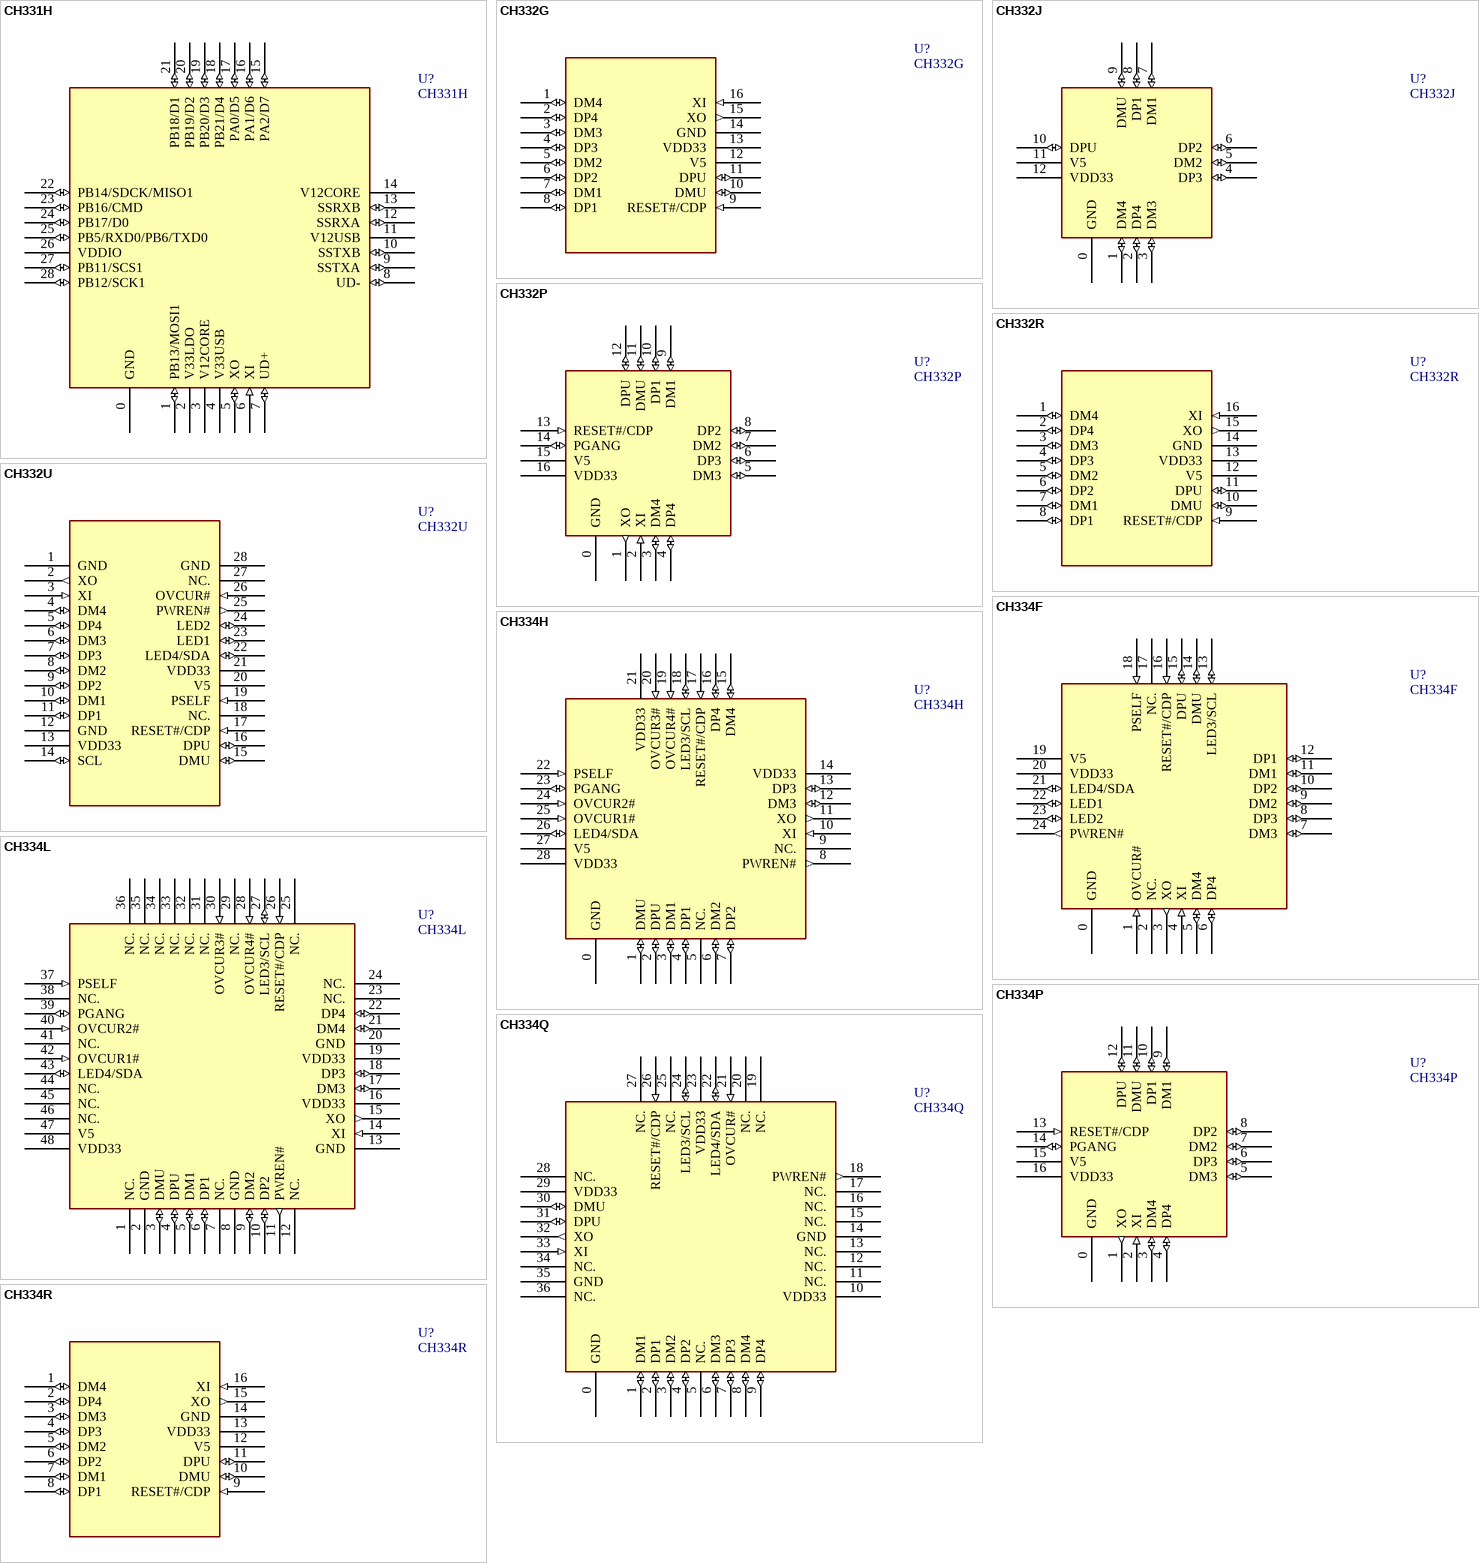
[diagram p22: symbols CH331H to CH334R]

## CH331H
designator U?
RISC-V USB 3.0 Disk Controller with AES/SM4
footprint QFN28_5X5
pins: 0 GND (power), 1 PB13/MOSI1 (io), 2 V33LDO (power), 3 V12CORE (power), 4 V33USB (power), 5 XO (io), 6 XI (in), 7 UD+ (io), 8 UD- (io), 9 SSTXA (io), 10 SSTXB (io), 11 V12USB (power), 12 SSRXA (io), 13 SSRXB (io), 14 V12CORE (power), 15 PA2/D7 (io), 16 PA1/D6 (io), 17 PA0/D5 (io), 18 PB21/D4 (io), 19 PB20/D3 (io), 20 PB19/D2 (io), 21 PB18/D1 (io), 22 PB14/SDCK/MISO1 (io), 23 PB16/CMD (io), 24 PB17/D0 (io), 25 PB5/RXD0/PB6/TXD0 (io), 26 VDDIO (power), 27 PB11/SCS1 (io), 28 PB12/SCK1 (io)

## CH332G
designator U?
4 ports High-Speed USB STT Hub
footprint SOP16 (Footprint not found)
pins: 1 DM4 (io), 2 DP4 (io), 3 DM3 (io), 4 DP3 (io), 5 DM2 (io), 6 DP2 (io), 7 DM1 (io), 8 DP1 (io), 9 RESET#/CDP (in), 10 DMU (io), 11 DPU (io), 12 V5 (power), 13 VDD33 (power), 14 GND (power), 15 XO (out), 16 XI (in)

## CH332J
designator U?
4 ports High-Speed USB STT Hub with internal oscillator
footprint QFN12_2X2
pins: 0 GND (power), 1 DM4 (io), 2 DP4 (io), 3 DM3 (io), 4 DP3 (io), 5 DM2 (io), 6 DP2 (io), 7 DM1 (io), 8 DP1 (io), 9 DMU (io), 10 DPU (io), 11 V5 (power), 12 VDD33 (power)

## CH332P
designator U?
4 ports High-Speed USB STT Hub
footprint QFN16_3X3 (Footprint not found)
pins: 0 GND (power), 1 XO (out), 2 XI (in), 3 DM4 (io), 4 DP4 (io), 5 DM3 (io), 6 DP3 (io), 7 DM2 (io), 8 DP2 (io), 9 DM1 (io), 10 DP1 (io), 11 DMU (io), 12 DPU (io), 13 RESET#/CDP (in), 14 PGANG (io), 15 V5 (power), 16 VDD33 (power)

## CH332R
designator U?
4 ports High-Speed USB STT Hub
footprint QSOP16 (Footprint not found)
pins: 1 DM4 (io), 2 DP4 (io), 3 DM3 (io), 4 DP3 (io), 5 DM2 (io), 6 DP2 (io), 7 DM1 (io), 8 DP1 (io), 9 RESET#/CDP (in), 10 DMU (io), 11 DPU (io), 12 V5 (power), 13 VDD33 (power), 14 GND (power), 15 XO (out), 16 XI (in)

## CH332U
designator U?
4 ports High-Speed USB STT Hub with over current detect & power control
footprint QSOP28 (Footprint not found)
pins: 1 GND (power), 2 XO (out), 3 XI (in), 4 DM4 (io), 5 DP4 (io), 6 DM3 (io), 7 DP3 (io), 8 DM2 (io), 9 DP2 (io), 10 DM1 (io), 11 DP1 (io), 12 GND (power), 13 VDD33 (power), 14 SCL (io), 15 DMU (io), 16 DPU (io), 17 RESET#/CDP (in), 18 NC., 19 PSELF (in), 20 V5 (power), 21 VDD33 (power), 22 LED4/SDA (io), 23 LED1 (io), 24 LED2 (io), 25 PWREN# (out), 26 OVCUR# (in), 27 NC., 28 GND (power)

## CH334F
designator U?
4 ports High-Speed USB MTT Hub with over current detect & power control
footprint QFN24_4X4 (Footprint not found)
pins: 0 GND (power), 1 OVCUR# (in), 2 NC., 3 XO (out), 4 XI (in), 5 DM4 (io), 6 DP4 (io), 7 DM3 (io), 8 DP3 (io), 9 DM2 (io), 10 DP2 (io), 11 DM1 (io), 12 DP1 (io), 13 LED3/SCL (io), 14 DMU (io), 15 DPU (io), 16 RESET#/CDP (in), 17 NC., 18 PSELF (in), 19 V5 (power), 20 VDD33 (power), 21 LED4/SDA (io), 22 LED1 (io), 23 LED2 (io), 24 PWREN# (out)

## CH334H
designator U?
4 ports High-Speed USB MTT Hub with 4 over current detect
footprint QFN28_5X5 (Footprint not found)
pins: 0 GND (power), 1 DMU (io), 2 DPU (io), 3 DM1 (io), 4 DP1 (io), 5 NC., 6 DM2 (io), 7 DP2 (io), 8 PWREN# (out), 9 NC., 10 XI (in), 11 XO (out), 12 DM3 (io), 13 DP3 (io), 14 VDD33 (power), 15 DM4 (io), 16 DP4 (io), 17 RESET#/CDP (in), 18 LED3/SCL (io), 19 OVCUR4# (in), 20 OVCUR3# (in), 21 VDD33 (power), 22 PSELF (in), 23 PGANG (io), 24 OVCUR2# (in), 25 OVCUR1# (in), 26 LED4/SDA (io), 27 V5 (power), 28 VDD33 (power)

## CH334L
designator U?
4 ports High-Speed USB MTT Hub with 4 over current detect
footprint LQFP48 (Footprint not found)
pins: 1 NC., 2 GND (power), 3 DMU (io), 4 DPU (io), 5 DM1 (io), 6 DP1 (io), 7 NC., 8 GND (power), 9 DM2 (io), 10 DP2 (io), 11 PWREN# (out), 12 NC., 13 GND (power), 14 XI (in), 15 XO (out), 16 VDD33 (power), 17 DM3 (io), 18 DP3 (io), 19 VDD33 (power), 20 GND (power), 21 DM4 (io), 22 DP4 (io), 23 NC., 24 NC., 25 NC., 26 RESET#/CDP (in), 27 LED3/SCL (io), 28 OVCUR4# (in), 29 NC., 30 OVCUR3# (in), 31 NC., 32 NC., 33 NC., 34 NC., 35 NC., 36 NC., 37 PSELF (in), 38 NC., 39 PGANG (io), 40 OVCUR2# (in), 41 NC., 42 OVCUR1# (in), 43 LED4/SDA (io), 44 NC., 45 NC., 46 NC., 47 V5 (power), 48 VDD33 (power)

## CH334P
designator U?
4 ports High-Speed USB MTT Hub
footprint QFN16_3X3 (Footprint not found)
pins: 0 GND (power), 1 XO (out), 2 XI (in), 3 DM4 (io), 4 DP4 (io), 5 DM3 (io), 6 DP3 (io), 7 DM2 (io), 8 DP2 (io), 9 DM1 (io), 10 DP1 (io), 11 DMU (io), 12 DPU (io), 13 RESET#/CDP (in), 14 PGANG (io), 15 V5 (power), 16 VDD33 (power)

## CH334Q
designator U?
4 ports High-Speed USB MTT Hub with over current detect & power control
footprint QFN36_6X6
pins: 0 GND (power), 1 DM1 (io), 2 DP1 (io), 3 DM2 (io), 4 DP2 (io), 5 NC., 6 DM3 (io), 7 DP3 (io), 8 DM4 (io), 9 DP4 (io), 10 VDD33 (power), 11 NC., 12 NC., 13 NC., 14 GND (power), 15 NC., 16 NC., 17 NC., 18 PWREN# (out), 19 NC., 20 NC., 21 OVCUR# (in), 22 LED4/SDA (io), 23 VDD33 (power), 24 LED3/SCL (io), 25 NC., 26 RESET#/CDP (in), 27 NC., 28 NC., 29 VDD33 (power), 30 DMU (io), 31 DPU (io), 32 XO (out), 33 XI (in), 34 NC., 35 GND (power), 36 NC.

## CH334R
designator U?
4 ports High-Speed USB MTT Hub
footprint QSOP16 (Footprint not found)
pins: 1 DM4 (io), 2 DP4 (io), 3 DM3 (io), 4 DP3 (io), 5 DM2 (io), 6 DP2 (io), 7 DM1 (io), 8 DP1 (io), 9 RESET#/CDP (in), 10 DMU (io), 11 DPU (io), 12 V5 (power), 13 VDD33 (power), 14 GND (power), 15 XO (out), 16 XI (in)

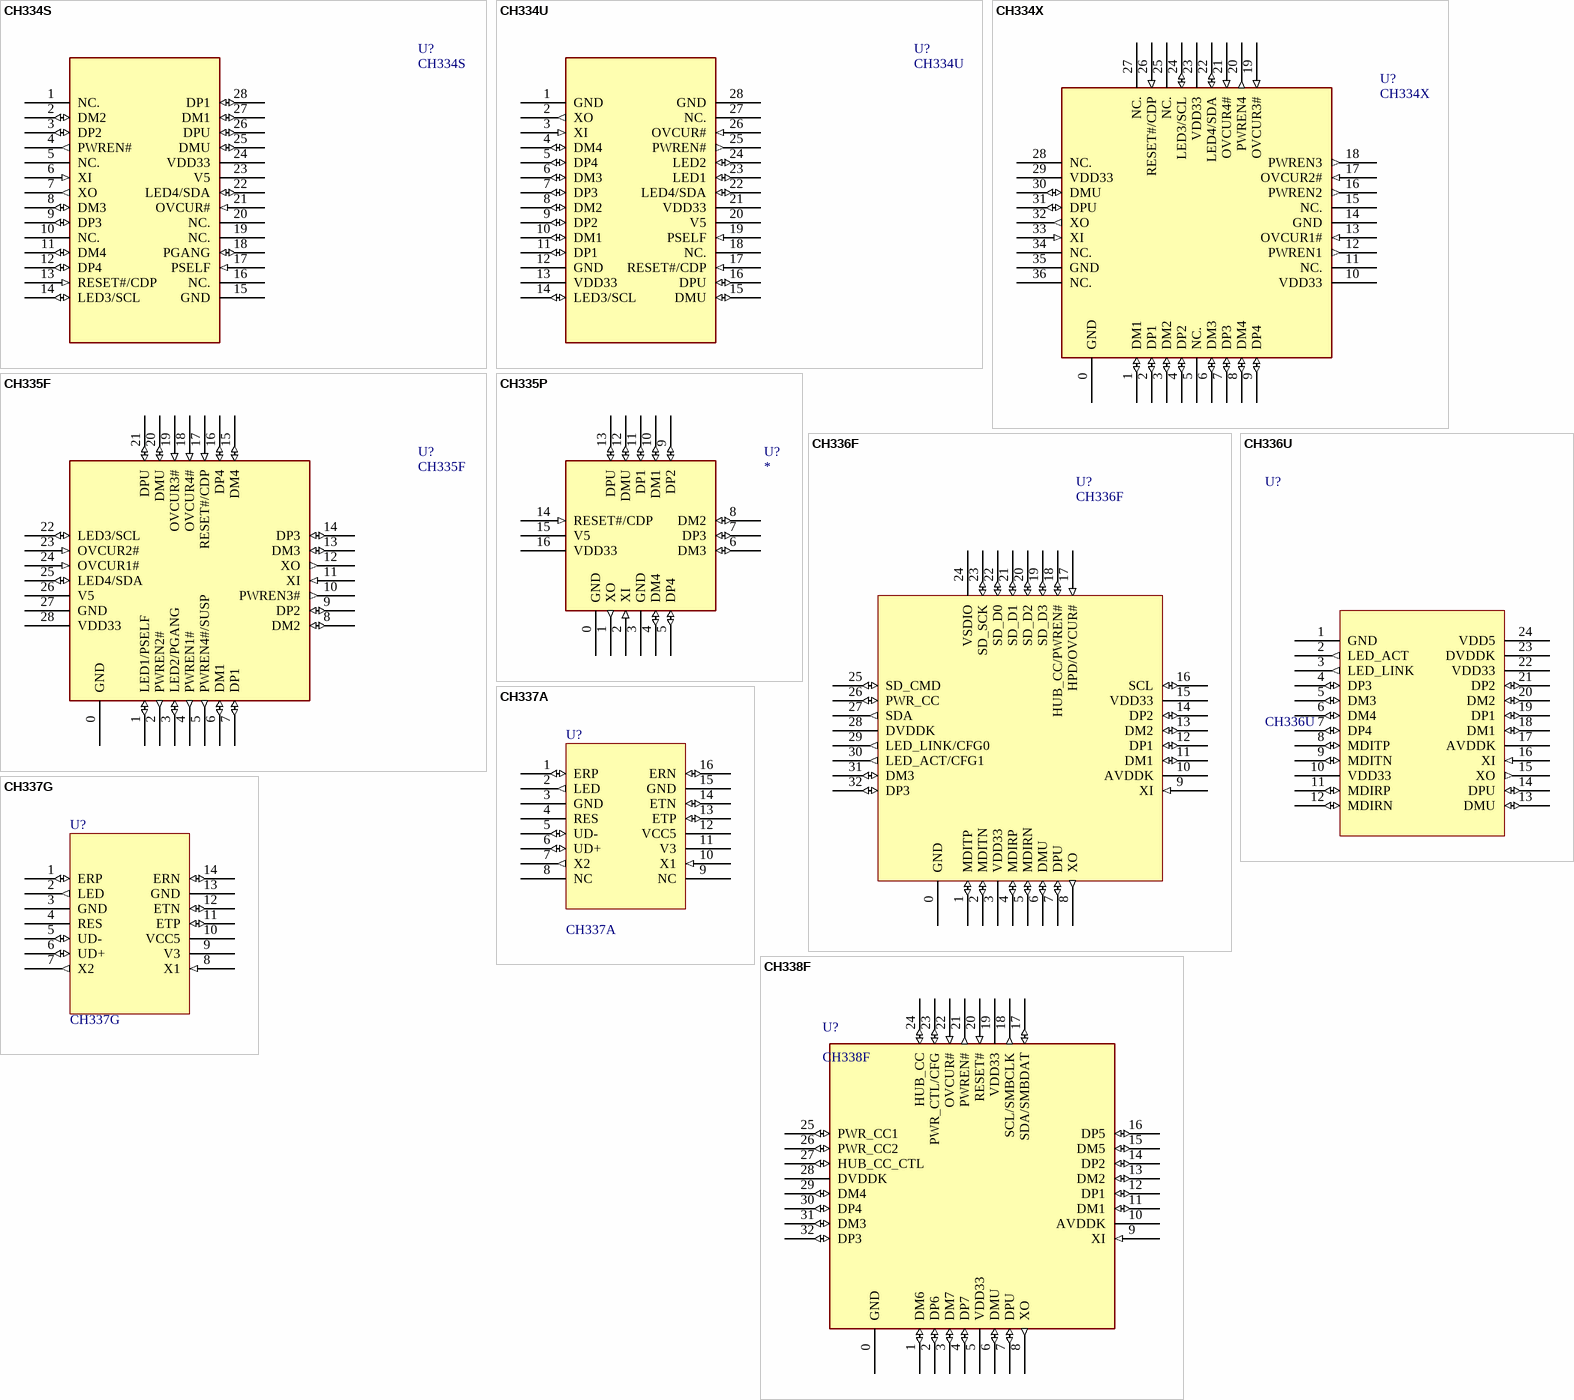
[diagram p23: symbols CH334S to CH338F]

## CH334S
designator U?
4 ports High-Speed USB MTT Hub with over current detect & power control
footprint SSOP28 (Footprint not found)
pins: 1 NC., 2 DM2 (io), 3 DP2 (io), 4 PWREN# (out), 5 NC., 6 XI (in), 7 XO (out), 8 DM3 (io), 9 DP3 (io), 10 NC., 11 DM4 (io), 12 DP4 (io), 13 RESET#/CDP (in), 14 LED3/SCL (io), 15 GND (power), 16 NC., 17 PSELF (in), 18 PGANG (io), 19 NC., 20 NC., 21 OVCUR# (in), 22 LED4/SDA (io), 23 V5 (power), 24 VDD33 (power), 25 DMU (io), 26 DPU (io), 27 DM1 (io), 28 DP1 (io)

## CH334U
designator U?
4 ports High-Speed USB MTT Hub with over current detect & power control
footprint QSOP28 (Footprint not found)
pins: 1 GND (power), 2 XO (out), 3 XI (in), 4 DM4 (io), 5 DP4 (io), 6 DM3 (io), 7 DP3 (io), 8 DM2 (io), 9 DP2 (io), 10 DM1 (io), 11 DP1 (io), 12 GND (power), 13 VDD33 (power), 14 LED3/SCL (io), 15 DMU (io), 16 DPU (io), 17 RESET#/CDP (in), 18 NC., 19 PSELF (in), 20 V5 (power), 21 VDD33 (power), 22 LED4/SDA (io), 23 LED1 (io), 24 LED2 (io), 25 PWREN# (out), 26 OVCUR# (in), 27 NC., 28 GND (power)

## CH334X
designator U?
4 ports High-Speed USB MTT Hub with 4 over current detect & power control
footprint QFN36_6X6
pins: 0 GND (power), 1 DM1 (io), 2 DP1 (io), 3 DM2 (io), 4 DP2 (io), 5 NC., 6 DM3 (io), 7 DP3 (io), 8 DM4 (io), 9 DP4 (io), 10 VDD33 (power), 11 NC., 12 PWREN1 (out), 13 OVCUR1# (in), 14 GND (power), 15 NC., 16 PWREN2 (out), 17 OVCUR2# (in), 18 PWREN3 (out), 19 OVCUR3# (in), 20 PWREN4 (out), 21 OVCUR4# (in), 22 LED4/SDA (io), 23 VDD33 (power), 24 LED3/SCL (io), 25 NC., 26 RESET#/CDP (in), 27 NC., 28 NC., 29 VDD33 (power), 30 DMU (io), 31 DPU (io), 32 XO (out), 33 XI (in), 34 NC., 35 GND (power), 36 NC.

## CH335F
designator U?
4 ports High-Speed USB MTT Hub with 4 over current detect & power control
footprint QFN28_4X4
pins: 0 GND (power), 1 LED1/PSELF (io), 2 PWREN2# (out), 3 LED2/PGANG (io), 4 PWREN1# (out), 5 PWREN4#/SUSP (out), 6 DM1 (io), 7 DP1 (io), 8 DM2 (io), 9 DP2 (io), 10 PWREN3# (out), 11 XI (in), 12 XO (out), 13 DM3 (io), 14 DP3 (io), 15 DM4 (io), 16 DP4 (io), 17 RESET#/CDP (in), 18 OVCUR4# (in), 19 OVCUR3# (in), 20 DMU (io), 21 DPU (io), 22 LED3/SCL (io), 23 OVCUR2# (in), 24 OVCUR1# (in), 25 LED4/SDA (io), 26 V5 (power), 27 GND (power), 28 VDD33 (power)

## CH335P
designator U?
4 ports High-Speed USB MTT Hub with internal oscillator
footprint QFN16C_2X2
pins: 0 GND (power), 1 XO (out), 2 XI (in), 3 GND (power), 4 DM4 (io), 5 DP4 (io), 6 DM3 (io), 7 DP3 (io), 8 DM2 (io), 9 DP2 (io), 10 DM1 (io), 11 DP1 (io), 12 DMU (io), 13 DPU (io), 14 RESET#/CDP (in), 15 V5 (power), 16 VDD33 (power)

## CH336F
designator U?
3 ports High-Speed USB MTT Hub with PD & SDIO & ethernet
footprint QFN32_4X4
pins: 0 GND (power), 1 MDITP (io), 2 MDITN (io), 3 VDD33 (power), 4 MDIRP (io), 5 MDIRN (io), 6 DMU (io), 7 DPU (io), 8 XO (out), 9 XI (in), 10 AVDDK (power), 11 DM1 (io), 12 DP1 (io), 13 DM2 (io), 14 DP2 (io), 15 VDD33 (power), 16 SCL (io), 17 HPD/OVCUR# (in), 18 HUB_CC/PWREN# (io), 19 SD_D3 (io), 20 SD_D2 (io), 21 SD_D1 (io), 22 SD_D0 (io), 23 SD_SCK (io), 24 VSDIO (power), 25 SD_CMD (io), 26 PWR_CC (io), 27 SDA (out), 28 DVDDK (power), 29 LED_LINK/CFG0 (out), 30 LED_ACT/CFG1 (out), 31 DM3 (io), 32 DP3 (io)

## CH336U
designator U?
4 ports High-Speed USB MTT Hub with ethernet
footprint QSOP24
pins: 1 GND (power), 2 LED_ACT (out), 3 LED_LINK (out), 4 DP3 (io), 5 DM3 (io), 6 DM4 (io), 7 DP4 (io), 8 MDITP (io), 9 MDITN (io), 10 VDD33 (power), 11 MDIRP (io), 12 MDIRN (io), 13 DMU (io), 14 DPU (io), 15 XO (out), 16 XI (in), 17 AVDDK (power), 18 DM1 (io), 19 DP1 (io), 20 DM2 (io), 21 DP2 (io), 22 VDD33 (power), 23 DVDDK (power), 24 VDD5 (power)

## CH337A
designator U?
USB to 10Mbps Ethernet
footprint SOP16
pins: 1 ERP (io), 2 LED (out), 3 GND (power), 4 RES, 5 UD- (io), 6 UD+ (io), 7 X2 (out), 8 NC, 9 NC, 10 X1 (in), 11 V3 (power), 12 VCC5 (power), 13 ETP (io), 14 ETN (io), 15 GND (power), 16 ERN (io)

## CH337G
designator U?
USB to 10Mbps Ethernet
footprint SOP14
pins: 1 ERP (io), 2 LED (out), 3 GND (power), 4 RES, 5 UD- (io), 6 UD+ (io), 7 X2 (out), 8 X1 (in), 9 V3 (power), 10 VCC5 (power), 11 ETP (io), 12 ETN (io), 13 GND (power), 14 ERN (io)

## CH338F
designator U?
7 ports High-Speed USB MTT Hub with PD
footprint QFN32_4X4
pins: 0 GND (power), 1 DM6 (io), 2 DP6 (io), 3 DM7 (io), 4 DP7 (io), 5 VDD33 (power), 6 DMU (io), 7 DPU (io), 8 XO (out), 9 XI (in), 10 AVDDK (power), 11 DM1 (io), 12 DP1 (io), 13 DM2 (io), 14 DP2 (io), 15 DM5 (io), 16 DP5 (io), 17 SDA/SMBDAT (io), 18 SCL/SMBCLK (out), 19 VDD33 (power), 20 RESET# (in), 21 PWREN# (out), 22 OVCUR# (in), 23 PWR_CTL/CFG (io), 24 HUB_CC (io), 25 PWR_CC1 (io), 26 PWR_CC2 (io), 27 HUB_CC_CTL (io), 28 DVDDK (power), 29 DM4 (io), 30 DP4 (io), 31 DM3 (io), 32 DP3 (io)

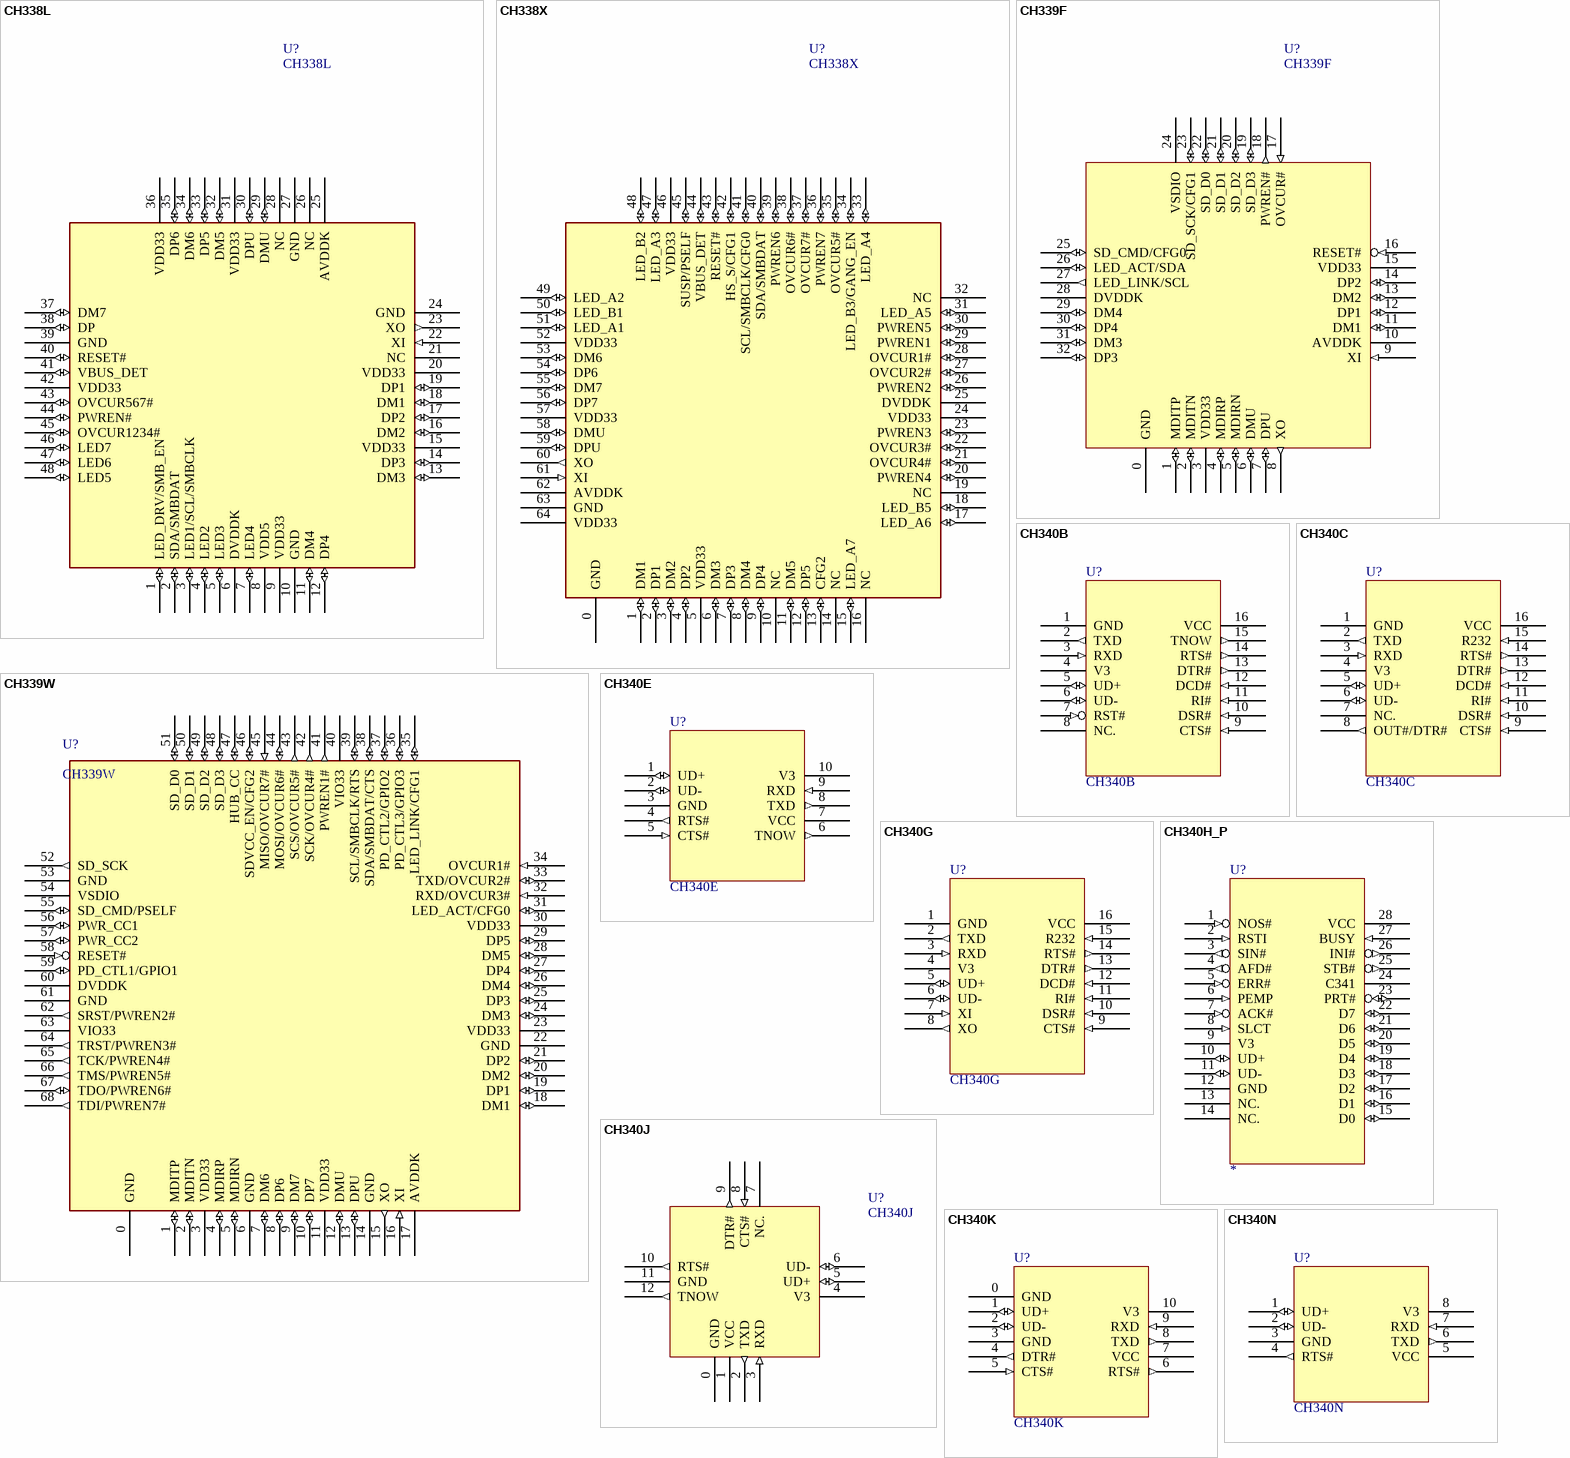
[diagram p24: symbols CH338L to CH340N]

## CH338L
designator U?
7 ports High-Speed USB MTT Hub
footprint LQFP48
pins: 1 LED_DRV/SMB_EN (io), 2 SDA/SMBDAT (io), 3 LED1/SCL/SMBCLK (io), 4 LED2 (io), 5 LED3 (io), 6 DVDDK (power), 7 LED4 (io), 8 VDD5 (power), 9 VDD33 (power), 10 GND (power), 11 DM4 (io), 12 DP4 (io), 13 DM3 (io), 14 DP3 (io), 15 VDD33 (power), 16 DM2 (io), 17 DP2 (io), 18 DM1 (io), 19 DP1 (io), 20 VDD33 (power), 21 NC, 22 XI (in), 23 XO (out), 24 GND (power), 25 AVDDK (power), 26 NC, 27 GND (power), 28 NC, 29 DMU (io), 30 DPU (io), 31 VDD33 (power), 32 DM5 (io), 33 DP5 (io), 34 DM6 (io), 35 DP6 (io), 36 VDD33 (power), 37 DM7 (io), 38 DP (io), 39 GND (power), 40 RESET# (io), 41 VBUS_DET (io), 42 VDD33 (power), 43 OVCUR567# (io), 44 PWREN# (io), 45 OVCUR1234# (io), 46 LED7 (io), 47 LED6 (io), 48 LED5 (io)

## CH338X
designator U?
7 ports High-Speed USB MTT Hub
footprint QFN64_9X9
pins: 0 GND (power), 1 DM1 (io), 2 DP1 (io), 3 DM2 (io), 4 DP2 (io), 5 VDD33 (power), 6 DM3 (io), 7 DP3 (io), 8 DM4 (io), 9 DP4 (io), 10 NC, 11 DM5 (io), 12 DP5 (io), 13 CFG2 (io), 14 NC, 15 LED_A7 (io), 16 NC, 17 LED_A6 (io), 18 LED_B5 (io), 19 NC, 20 PWREN4 (io), 21 OVCUR4# (io), 22 OVCUR3# (io), 23 PWREN3 (io), 24 VDD33 (power), 25 DVDDK (power), 26 PWREN2 (io), 27 OVCUR2# (io), 28 OVCUR1# (io), 29 PWREN1 (io), 30 PWREN5 (io), 31 LED_A5 (io), 32 NC, 33 LED_A4 (io), 34 LED_B3/GANG_EN (io), 35 OVCUR5# (io), 36 PWREN7 (io), 37 OVCUR7# (io), 38 OVCUR6# (io), 39 PWREN6 (io), 40 SDA/SMBDAT (io), 41 SCL/SMBCLK/CFG0 (io), 42 HS_S/CFG1 (io), 43 RESET# (io), 44 VBUS_DET (io), 45 SUSP/PSELF (io), 46 VDD33 (power), 47 LED_A3 (io), 48 LED_B2 (io), 49 LED_A2 (io), 50 LED_B1 (io), 51 LED_A1 (io), 52 VDD33 (power), 53 DM6 (io), 54 DP6 (io), 55 DM7 (io), 56 DP7 (io), 57 VDD33 (power), 58 DMU (io), 59 DPU (io), 60 XO (out), 61 XI (in), 62 AVDDK (power), 63 GND (power), 64 VDD33 (power)

## CH339F
designator U?
4 ports High-Speed USB MTT Hub with SDIO & ethernet
footprint QFN32_4X4
pins: 0 GND (power), 1 MDITP (io), 2 MDITN (io), 3 VDD33 (power), 4 MDIRP (io), 5 MDIRN (io), 6 DMU (io), 7 DPU (io), 8 XO (out), 9 XI (in), 10 AVDDK (power), 11 DM1 (io), 12 DP1 (io), 13 DM2 (io), 14 DP2 (io), 15 VDD33 (power), 16 RESET# (in), 17 OVCUR# (in), 18 PWREN# (out), 19 SD_D3 (io), 20 SD_D2 (io), 21 SD_D1 (io), 22 SD_D0 (io), 23 SD_SCK/CFG1 (io), 24 VSDIO (power), 25 SD_CMD/CFG0 (io), 26 LED_ACT/SDA (io), 27 LED_LINK/SCL (out), 28 DVDDK (power), 29 DM4 (io), 30 DP4 (io), 31 DM3 (io), 32 DP3 (io)

## CH339W
designator U?
7 ports High-Speed USB MTT Hub with PD & SDIO & ethernet
footprint QFN68_8X8
pins: 0 GND (power), 1 MDITP (io), 2 MDITN (io), 3 VDD33 (power), 4 MDIRP (io), 5 MDIRN (io), 6 GND (power), 7 DM6 (io), 8 DP6 (io), 9 DM7 (io), 10 DP7 (io), 11 VDD33 (power), 12 DMU (io), 13 DPU (io), 14 GND (power), 15 XO (out), 16 XI (in), 17 AVDDK (power), 18 DM1 (io), 19 DP1 (io), 20 DM2 (io), 21 DP2 (io), 22 GND (power), 23 VDD33 (power), 24 DM3 (io), 25 DP3 (io), 26 DM4 (io), 27 DP4 (io), 28 DM5 (io), 29 DP5 (io), 30 VDD33 (power), 31 LED_ACT/CFG0 (io), 32 RXD/OVCUR3# (in), 33 TXD/OVCUR2# (io), 34 OVCUR1# (in), 35 LED_LINK/CFG1 (io), 36 PD_CTL3/GPIO3 (io), 37 PD_CTL2/GPIO2 (io), 38 SDA/SMBDAT/CTS (io), 39 SCL/SMBCLK/RTS (io), 40 VIO33 (power), 41 PWREN1# (out), 42 SCK/OVCUR4# (out), 43 SCS/OVCUR5# (out), 44 MOSI/OVCUR6# (io), 45 MISO/OVCUR7# (in), 46 SDVCC_EN/CFG2 (io), 47 HUB_CC (io), 48 SD_D3 (io), 49 SD_D2 (io), 50 SD_D1 (io), 51 SD_D0 (io), 52 SD_SCK (out), 53 GND (power), 54 VSDIO (power), 55 SD_CMD/PSELF (io), 56 PWR_CC1 (io), 57 PWR_CC2 (io), 58 RESET# (in), 59 PD_CTL1/GPIO1 (io), 60 DVDDK (power), 61 GND (power), 62 SRST/PWREN2# (out), 63 VIO33 (power), 64 TRST/PWREN3# (out), 65 TCK/PWREN4# (out), 66 TMS/PWREN5# (out), 67 TDO/PWREN6# (io), 68 TDI/PWREN7# (out)

## CH340B
designator U?
USB to TTL Serial / UART, Integrated clock
footprint SOP16
pins: 1 GND (power), 2 TXD (out), 3 RXD (in), 4 V3 (power), 5 UD+ (io), 6 UD- (io), 7 RST# (in), 8 NC., 9 CTS# (in), 10 DSR# (in), 11 RI# (in), 12 DCD# (in), 13 DTR# (out), 14 RTS# (out), 15 TNOW (out), 16 VCC (power)

## CH340C
designator U?
USB to TTL Serial / UART
footprint SOP16
pins: 1 GND (power), 2 TXD (out), 3 RXD (in), 4 V3 (power), 5 UD+ (io), 6 UD- (io), 7 NC., 8 OUT#/DTR# (out), 9 CTS# (in), 10 DSR# (in), 11 RI# (in), 12 DCD# (in), 13 DTR# (out), 14 RTS# (out), 15 R232 (in), 16 VCC (power)

## CH340E
designator U?
USB to TTL Serial / UART
footprint MSOP10
pins: 1 UD+ (io), 2 UD- (io), 3 GND (power), 4 RTS# (out), 5 CTS# (in), 6 TNOW (out), 7 VCC (power), 8 TXD (out), 9 RXD (in), 10 V3 (power)

## CH340G
designator U?
USB to TTL Serial / UART
footprint SOP16
pins: 1 GND (power), 2 TXD (out), 3 RXD (in), 4 V3 (power), 5 UD+ (io), 6 UD- (io), 7 XI (in), 8 XO (out), 9 CTS# (in), 10 DSR# (in), 11 RI# (in), 12 DCD# (in), 13 DTR# (out), 14 RTS# (out), 15 R232 (in), 16 VCC (power)

## CH340H_P
designator U?
USB to Print Port / Parallel
footprint SOP28
footprint DIP28
pins: 1 NOS# (in), 2 RSTI (in), 3 SIN# (out), 4 AFD# (out), 5 ERR# (in), 6 PEMP (in), 7 ACK# (in), 8 SLCT (in), 9 V3 (power), 10 UD+ (io), 11 UD- (io), 12 GND (power), 13 NC., 14 NC., 15 D0 (io), 16 D1 (io), 17 D2 (io), 18 D3 (io), 19 D4 (io), 20 D5 (io), 21 D6 (io), 22 D7 (io), 23 PRT# (io), 24 C341, 25 STB# (out), 26 INI# (out), 27 BUSY (in), 28 VCC (power)

## CH340J
designator U?
USB to TTL Serial / UART
footprint QFN12_2X2
pins: 0 GND (power), 1 VCC (power), 2 TXD (out), 3 RXD (in), 4 V3 (power), 5 UD+ (io), 6 UD- (io), 7 NC., 8 CTS# (in), 9 DTR# (out), 10 RTS# (out), 11 GND (power), 12 TNOW (out)

## CH340K
designator U?
USB to TTL Serial / UART for dual power
footprint ESSOP10
pins: 0 GND (power), 1 UD+ (io), 2 UD- (io), 3 GND (power), 4 DTR# (out), 5 CTS# (in), 6 RTS# (out), 7 VCC (power), 8 TXD (out), 9 RXD (in), 10 V3 (power)

## CH340N
designator U?
USB to TTL Serial / UART
footprint SOP8
pins: 1 UD+ (io), 2 UD- (io), 3 GND (power), 4 RTS# (out), 5 VCC (power), 6 TXD (out), 7 RXD (in), 8 V3 (power)

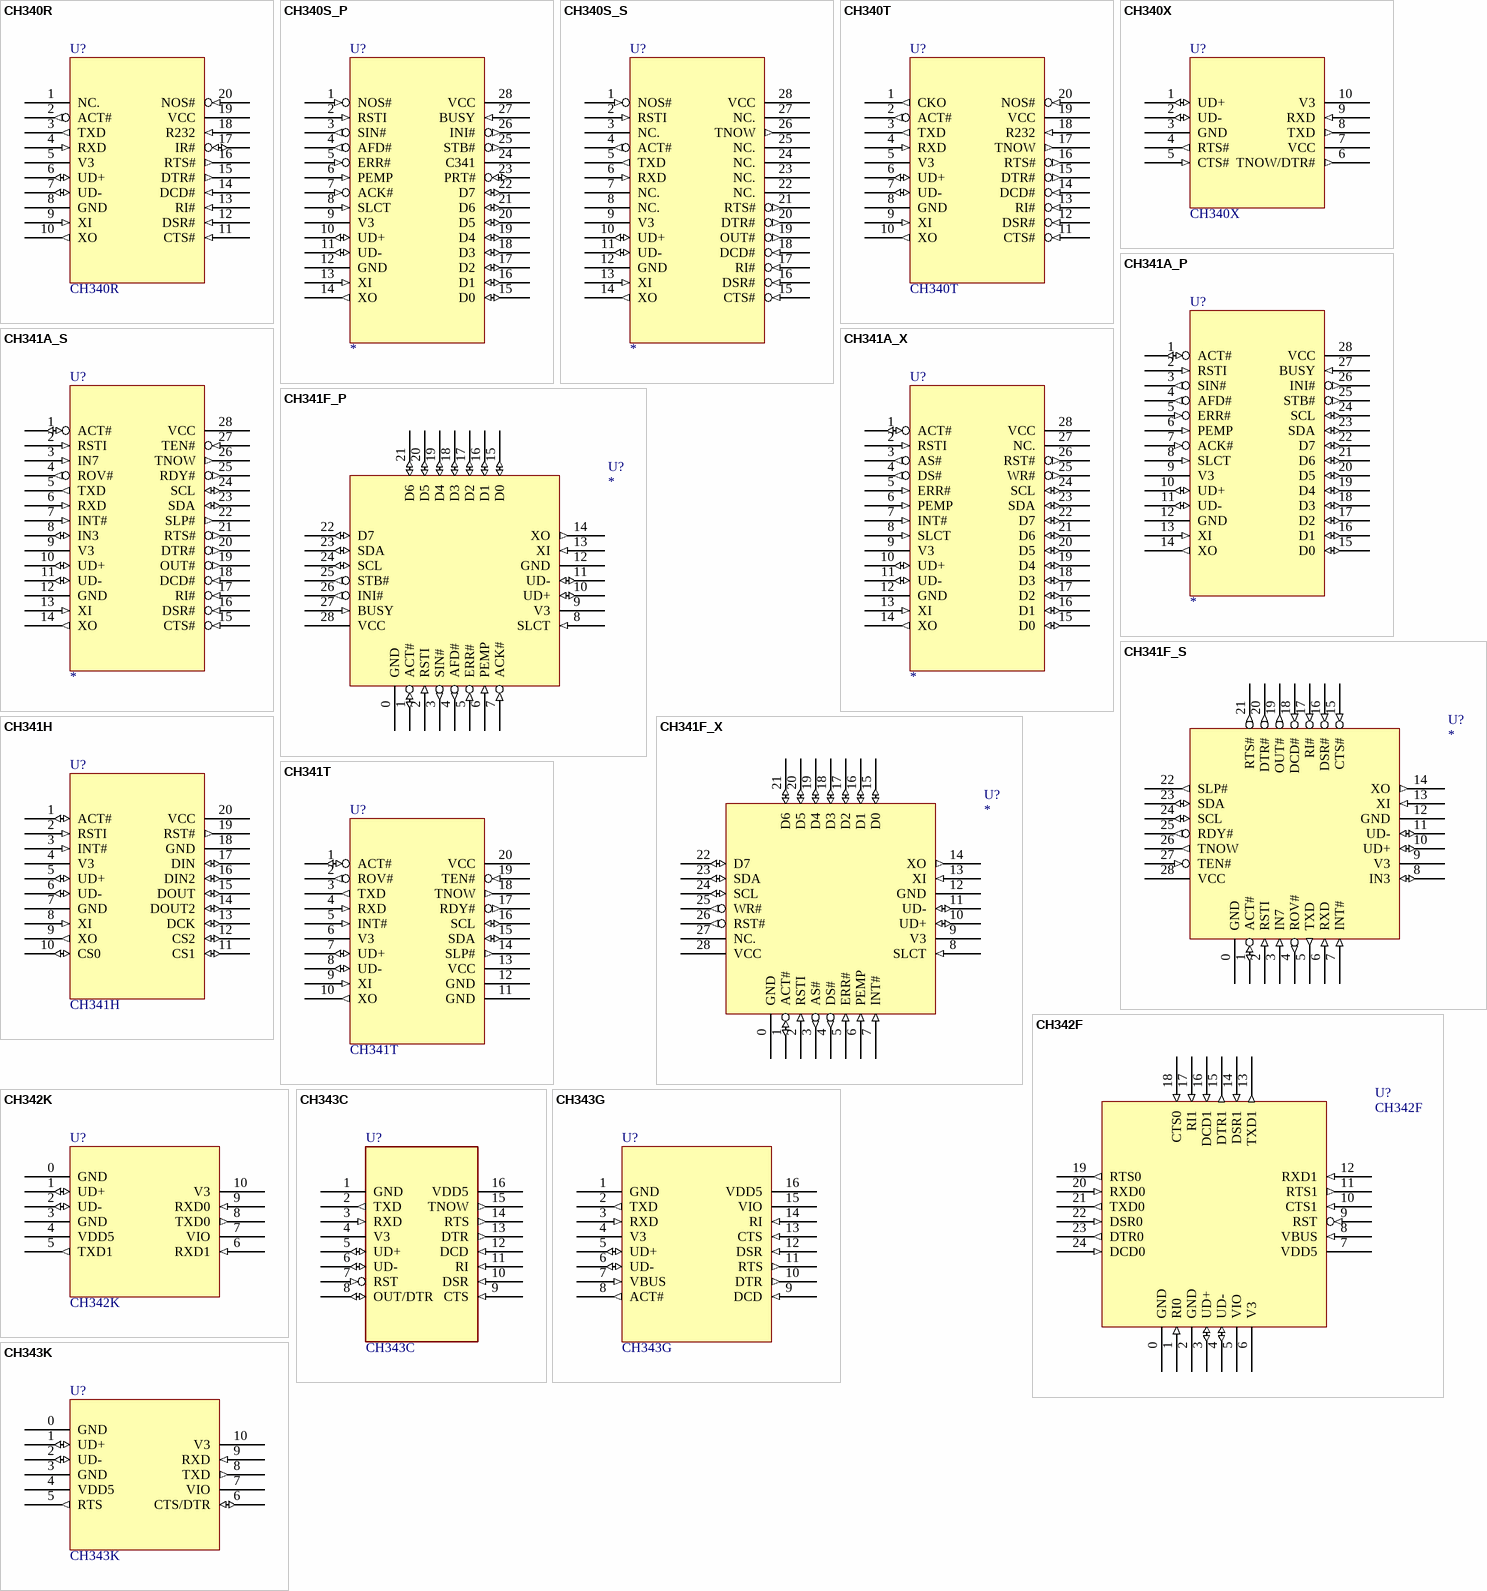
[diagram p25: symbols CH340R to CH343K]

## CH340R
designator U?
USB to IrDA, USB to RS232 Serial
footprint SSOP20
pins: 1 NC., 2 ACT# (out), 3 TXD (out), 4 RXD (in), 5 V3 (power), 6 UD+ (io), 7 UD- (io), 8 GND (power), 9 XI (in), 10 XO (out), 11 CTS# (in), 12 DSR# (in), 13 RI# (in), 14 DCD# (in), 15 DTR# (out), 16 RTS# (out), 17 IR# (io), 18 R232 (in), 19 VCC (power), 20 NOS# (in)

## CH340S_P
designator U?
USB to Print Port / Parallel
footprint SOP28
footprint DIP28
pins: 1 NOS# (in), 2 RSTI (in), 3 SIN# (out), 4 AFD# (out), 5 ERR# (in), 6 PEMP (in), 7 ACK# (in), 8 SLCT (in), 9 V3 (power), 10 UD+ (io), 11 UD- (io), 12 GND (power), 13 XI (in), 14 XO (out), 15 D0 (io), 16 D1 (io), 17 D2 (io), 18 D3 (io), 19 D4 (io), 20 D5 (io), 21 D6 (io), 22 D7 (io), 23 PRT# (io), 24 C341, 25 STB# (out), 26 INI# (out), 27 BUSY (in), 28 VCC (power)

## CH340S_S
designator U?
USB to TTL Serial / UART, pin compatible with CH341
footprint SOP28
footprint DIP28
pins: 1 NOS# (in), 2 RSTI (in), 3 NC., 4 ACT# (out), 5 TXD (out), 6 RXD (in), 7 NC., 8 NC., 9 V3 (power), 10 UD+ (io), 11 UD- (io), 12 GND (power), 13 XI (in), 14 XO (out), 15 CTS# (in), 16 DSR# (in), 17 RI# (in), 18 DCD# (in), 19 OUT# (out), 20 DTR# (out), 21 RTS# (out), 22 NC., 23 NC., 24 NC., 25 NC., 26 TNOW (out), 27 NC., 28 VCC (power)

## CH340T
designator U?
USB to TTL Serial / UART,  USB to IrDA
footprint SSOP20
pins: 1 CKO (out), 2 ACT# (out), 3 TXD (out), 4 RXD (in), 5 V3 (power), 6 UD+ (io), 7 UD- (io), 8 GND (power), 9 XI (in), 10 XO (out), 11 CTS# (in), 12 DSR# (in), 13 RI# (in), 14 DCD# (in), 15 DTR# (out), 16 RTS# (out), 17 TNOW (out), 18 R232 (in), 19 VCC (power), 20 NOS# (in)

## CH340X
designator U?
USB to TTL Serial / UART
footprint MSOP10
pins: 1 UD+ (io), 2 UD- (io), 3 GND (power), 4 RTS# (out), 5 CTS# (in), 6 TNOW/DTR# (out), 7 VCC (power), 8 TXD (out), 9 RXD (in), 10 V3 (power)

## CH341A_P
designator U?
USB to Print Port / Parallel
footprint SOP28
footprint TSSOP28
footprint DIP28
pins: 1 ACT# (io), 2 RSTI (in), 3 SIN# (out), 4 AFD# (out), 5 ERR# (in), 6 PEMP (in), 7 ACK# (in), 8 SLCT (in), 9 V3 (power), 10 UD+ (io), 11 UD- (io), 12 GND (power), 13 XI (in), 14 XO (out), 15 D0 (io), 16 D1 (io), 17 D2 (io), 18 D3 (io), 19 D4 (io), 20 D5 (io), 21 D6 (io), 22 D7 (io), 23 SDA (io), 24 SCL (io), 25 STB# (out), 26 INI# (out), 27 BUSY (in), 28 VCC (power)

## CH341A_S
designator U?
USB to TTL Serial / UART / I2C/IIC
footprint SOP28
footprint TSSOP28
footprint DIP28
pins: 1 ACT# (io), 2 RSTI (in), 3 IN7 (in), 4 ROV# (out), 5 TXD (out), 6 RXD (in), 7 INT# (in), 8 IN3 (io), 9 V3 (power), 10 UD+ (io), 11 UD- (io), 12 GND (power), 13 XI (in), 14 XO (out), 15 CTS# (in), 16 DSR# (in), 17 RI# (in), 18 DCD# (in), 19 OUT# (out), 20 DTR# (out), 21 RTS# (out), 22 SLP# (out), 23 SDA (io), 24 SCL (io), 25 RDY# (out), 26 TNOW (out), 27 TEN# (in), 28 VCC (power)

## CH341A_X
designator U?
USB to EPP Parallel / SPI / I2C/IIC
footprint SOP28
footprint TSSOP28
footprint DIP28
pins: 1 ACT# (io), 2 RSTI (in), 3 AS# (out), 4 DS# (out), 5 ERR# (in), 6 PEMP (in), 7 INT# (in), 8 SLCT (in), 9 V3 (power), 10 UD+ (io), 11 UD- (io), 12 GND (power), 13 XI (in), 14 XO (out), 15 D0 (io), 16 D1 (io), 17 D2 (io), 18 D3 (io), 19 D4 (io), 20 D5 (io), 21 D6 (io), 22 D7 (io), 23 SDA (io), 24 SCL (io), 25 WR# (out), 26 RST# (out), 27 NC., 28 VCC (power)

## CH341F_P
designator U?
USB to Print Port / Parallel
footprint QFN28_4X4
footprint DIP28
pins: 0 GND (power), 1 ACT# (io), 2 RSTI (in), 3 SIN# (out), 4 AFD# (out), 5 ERR# (in), 6 PEMP (in), 7 ACK# (in), 8 SLCT (in), 9 V3 (power), 10 UD+ (io), 11 UD- (io), 12 GND (power), 13 XI (in), 14 XO (out), 15 D0 (io), 16 D1 (io), 17 D2 (io), 18 D3 (io), 19 D4 (io), 20 D5 (io), 21 D6 (io), 22 D7 (io), 23 SDA (io), 24 SCL (io), 25 STB# (out), 26 INI# (out), 27 BUSY (in), 28 VCC (power)

## CH341F_S
designator U?
USB to TTL Serial / UART / I2C/IIC
footprint QFN28_4X4
footprint DIP28
pins: 0 GND (power), 1 ACT# (io), 2 RSTI (in), 3 IN7 (in), 4 ROV# (out), 5 TXD (out), 6 RXD (in), 7 INT# (in), 8 IN3 (io), 9 V3 (power), 10 UD+ (io), 11 UD- (io), 12 GND (power), 13 XI (in), 14 XO (out), 15 CTS# (in), 16 DSR# (in), 17 RI# (in), 18 DCD# (in), 19 OUT# (out), 20 DTR# (out), 21 RTS# (out), 22 SLP# (out), 23 SDA (io), 24 SCL (io), 25 RDY# (out), 26 TNOW (out), 27 TEN# (in), 28 VCC (power)

## CH341F_X
designator U?
USB to EPP Parallel / SPI / I2C/IIC
footprint QFN28_4X4
footprint DIP28
pins: 0 GND (power), 1 ACT# (io), 2 RSTI (in), 3 AS# (out), 4 DS# (out), 5 ERR# (in), 6 PEMP (in), 7 INT# (in), 8 SLCT (in), 9 V3 (power), 10 UD+ (io), 11 UD- (io), 12 GND (power), 13 XI (in), 14 XO (out), 15 D0 (io), 16 D1 (io), 17 D2 (io), 18 D3 (io), 19 D4 (io), 20 D5 (io), 21 D6 (io), 22 D7 (io), 23 SDA (io), 24 SCL (io), 25 WR# (out), 26 RST# (out), 27 NC., 28 VCC (power)

## CH341H
designator U?
USB to SPI
footprint SSOP20
pins: 1 ACT# (io), 2 RSTI (in), 3 INT# (in), 4 V3 (power), 5 UD+ (io), 6 UD- (io), 7 GND (power), 8 XI (in), 9 XO (out), 10 CS0 (io), 11 CS1 (io), 12 CS2 (io), 13 DCK (io), 14 DOUT2 (io), 15 DOUT (io), 16 DIN2 (io), 17 DIN (io), 18 GND (power), 19 RST# (out), 20 VCC (power)

## CH341T
designator U?
USB to TTL Serial / UART / I2C/IIC
footprint SSOP20
pins: 1 ACT# (io), 2 ROV# (out), 3 TXD (out), 4 RXD (in), 5 INT# (in), 6 V3 (power), 7 UD+ (io), 8 UD- (io), 9 XI (in), 10 XO (out), 11 GND (power), 12 GND (power), 13 VCC (power), 14 SLP# (out), 15 SDA (io), 16 SCL (io), 17 RDY# (out), 18 TNOW (out), 19 TEN# (in), 20 VCC (power)

## CH342F
designator U?
USB to dual enhanced TTL Serial / 2*UART
footprint QFN24_4X4
pins: 0 GND (power), 1 RI0 (in), 2 GND (power), 3 UD+ (io), 4 UD- (io), 5 VIO (power), 6 V3 (power), 7 VDD5 (power), 8 VBUS (in), 9 RST (in), 10 CTS1 (in), 11 RTS1 (out), 12 RXD1 (in), 13 TXD1 (out), 14 DSR1 (in), 15 DTR1 (out), 16 DCD1 (in), 17 RI1 (in), 18 CTS0 (in), 19 RTS0 (out), 20 RXD0 (in), 21 TXD0 (out), 22 DSR0 (in), 23 DTR0 (out), 24 DCD0 (in)

## CH342K
designator U?
USB to dual enhanced TTL Serial / 2*UART
footprint ESSOP10
pins: 0 GND (power), 1 UD+ (io), 2 UD- (io), 3 GND (power), 4 VDD5 (power), 5 TXD1 (out), 6 RXD1 (in), 7 VIO (power), 8 TXD0 (out), 9 RXD0 (in), 10 V3 (power)

## CH343C
designator U?
USB to high speed enhanced TTL Serial / UART
footprint SOP16
pins: 1 GND (power), 2 TXD (out), 3 RXD (in), 4 V3 (power), 5 UD+ (io), 6 UD- (io), 7 RST (in), 8 OUT/DTR (io), 9 CTS (in), 10 DSR (in), 11 RI (in), 12 DCD (in), 13 DTR (out), 14 RTS (out), 15 TNOW (out), 16 VDD5 (power)

## CH343G
designator U?
USB to high speed enhanced TTL Serial / UART
footprint SOP16
footprint DIP16
pins: 1 GND (power), 2 TXD (out), 3 RXD (in), 4 V3 (power), 5 UD+ (io), 6 UD- (io), 7 VBUS (in), 8 ACT# (out), 9 DCD (in), 10 DTR (out), 11 RTS (out), 12 DSR (in), 13 CTS (in), 14 RI (in), 15 VIO (power), 16 VDD5 (power)

## CH343K
designator U?
USB to high speed enhanced TTL Serial / UART
footprint ESSOP10
pins: 0 GND (power), 1 UD+ (io), 2 UD- (io), 3 GND (power), 4 VDD5 (power), 5 RTS (out), 6 CTS/DTR (io), 7 VIO (power), 8 TXD (out), 9 RXD (in), 10 V3 (power)

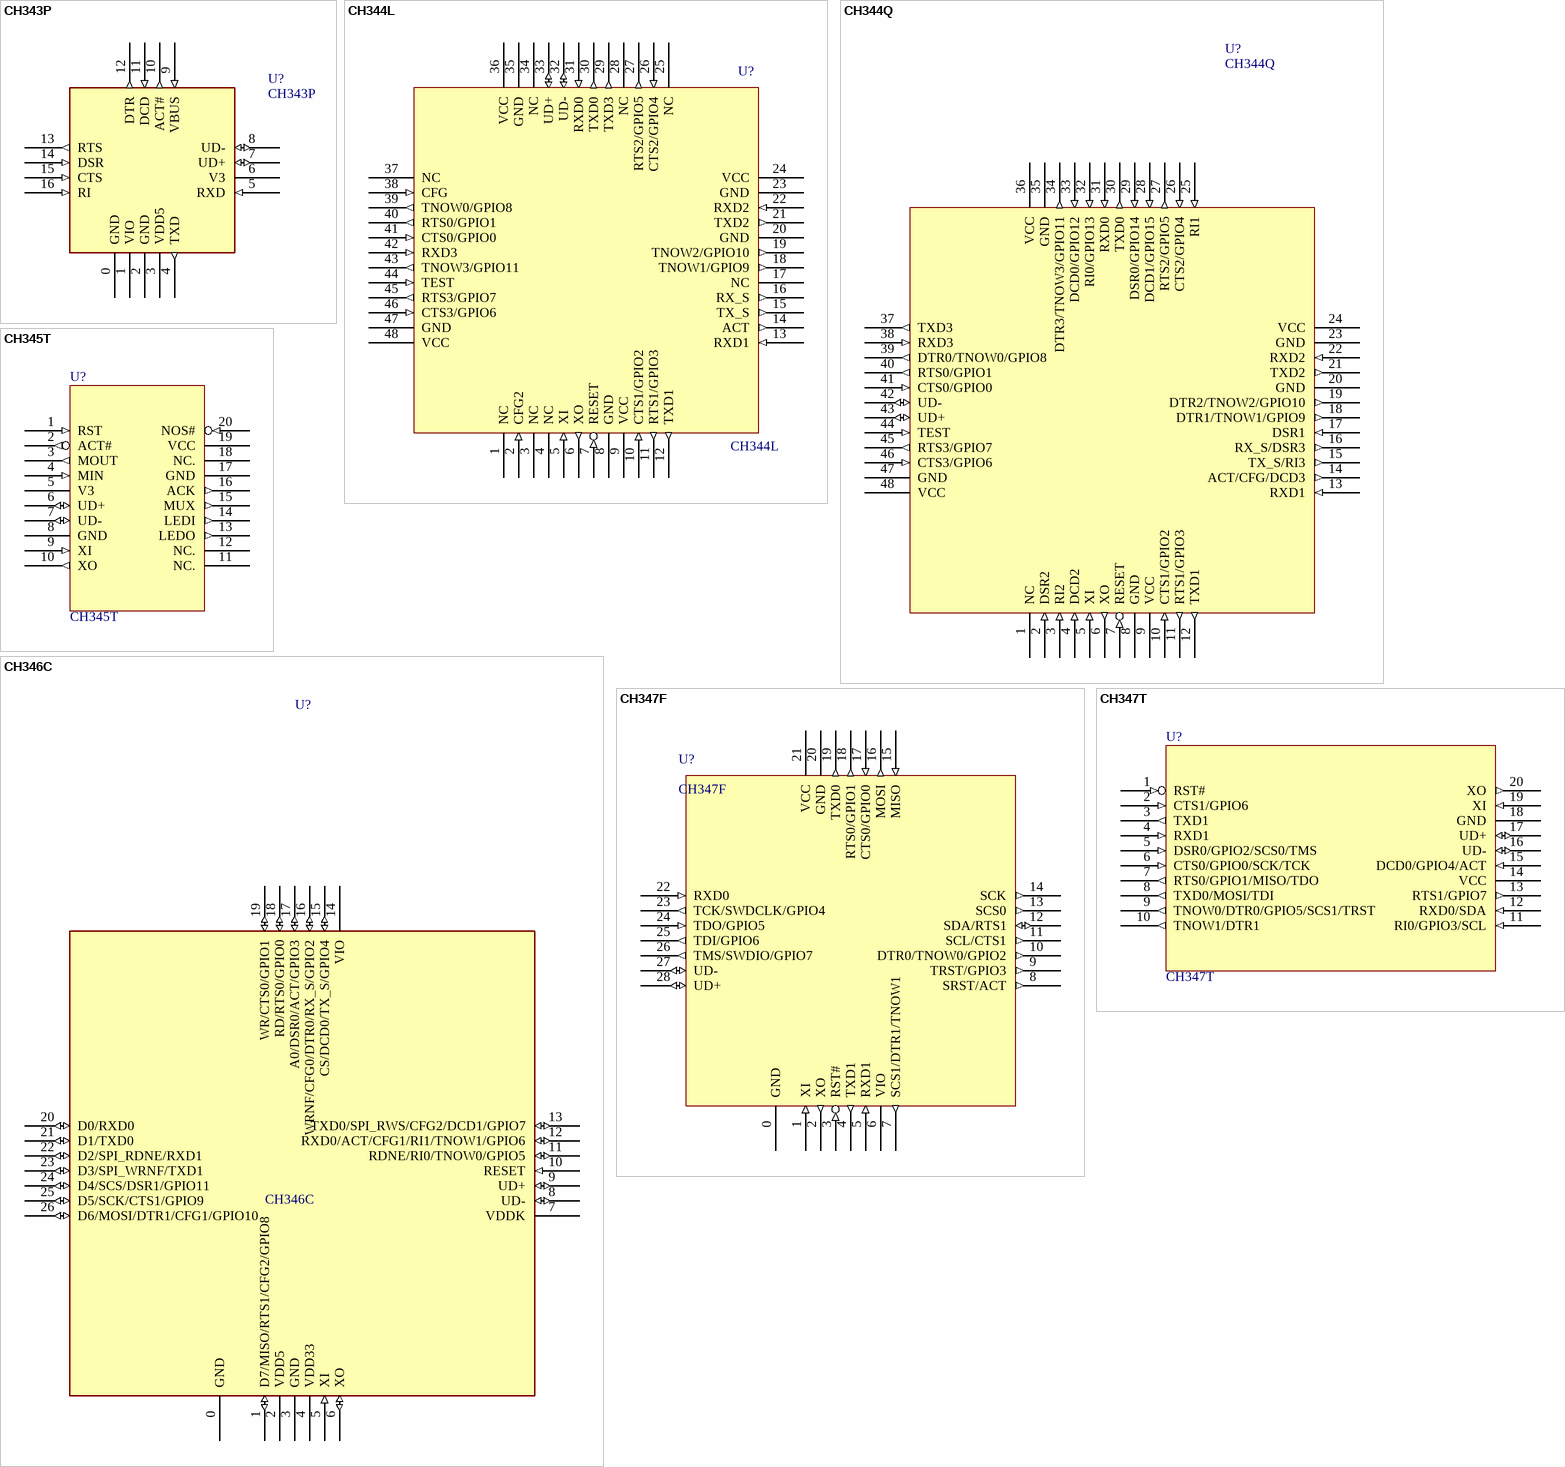
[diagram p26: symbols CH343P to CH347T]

## CH343P
designator U?
USB to high speed enhanced TTL Serial / UART
footprint QFN16_3X3 (Footprint not found)
pins: 0 GND (power), 1 VIO (power), 2 GND (power), 3 VDD5 (power), 4 TXD (out), 5 RXD (in), 6 V3 (power), 7 UD+ (io), 8 UD- (io), 9 VBUS (in), 10 ACT# (out), 11 DCD (in), 12 DTR (out), 13 RTS (out), 14 DSR (in), 15 CTS (in), 16 RI (in)

## CH344L
designator U?
USB to quad serial port / 4*UART
footprint LQFP48 (Footprint not found)
pins: 1 NC, 2 CFG2 (in), 3 NC, 4 NC, 5 XI (in), 6 XO (out), 7 RESET (in), 8 GND (power), 9 VCC (power), 10 CTS1/GPIO2 (in), 11 RTS1/GPIO3 (out), 12 TXD1 (out), 13 RXD1 (in), 14 ACT (out), 15 TX_S (out), 16 RX_S (out), 17 NC, 18 TNOW1/GPIO9 (out), 19 TNOW2/GPIO10 (out), 20 GND (power), 21 TXD2 (out), 22 RXD2 (in), 23 GND (power), 24 VCC (power), 25 NC, 26 CTS2/GPIO4 (in), 27 RTS2/GPIO5 (out), 28 NC, 29 TXD3 (out), 30 TXD0 (out), 31 RXD0 (in), 32 UD- (io), 33 UD+ (io), 34 NC, 35 GND (power), 36 VCC (power), 37 NC, 38 CFG (in), 39 TNOW0/GPIO8 (out), 40 RTS0/GPIO1 (out), 41 CTS0/GPIO0 (in), 42 RXD3 (in), 43 TNOW3/GPIO11 (out), 44 TEST (in), 45 RTS3/GPIO7 (out), 46 CTS3/GPIO6 (in), 47 GND (power), 48 VCC (power)

## CH344Q
designator U?
High Speed USB to quad serial port / 4*UART
footprint LQFP48 (Footprint not found)
pins: 1 NC, 2 DSR2 (in), 3 RI2 (in), 4 DCD2 (in), 5 XI (in), 6 XO (out), 7 RESET (in), 8 GND (power), 9 VCC (power), 10 CTS1/GPIO2 (in), 11 RTS1/GPIO3 (out), 12 TXD1 (out), 13 RXD1 (in), 14 ACT/CFG/DCD3 (out), 15 TX_S/RI3 (out), 16 RX_S/DSR3 (out), 17 DSR1 (in), 18 DTR1/TNOW1/GPIO9 (out), 19 DTR2/TNOW2/GPIO10 (out), 20 GND (power), 21 TXD2 (out), 22 RXD2 (in), 23 GND (power), 24 VCC (power), 25 RI1 (in), 26 CTS2/GPIO4 (in), 27 RTS2/GPIO5 (out), 28 DCD1/GPIO15 (in), 29 DSR0/GPIO14 (in), 30 TXD0 (out), 31 RXD0 (in), 32 RI0/GPIO13 (in), 33 DCD0/GPIO12 (in), 34 DTR3/TNOW3/GPIO11 (out), 35 GND (power), 36 VCC (power), 37 TXD3 (out), 38 RXD3 (in), 39 DTR0/TNOW0/GPIO8 (out), 40 RTS0/GPIO1 (out), 41 CTS0/GPIO0 (in), 42 UD- (io), 43 UD+ (io), 44 TEST (in), 45 RTS3/GPIO7 (out), 46 CTS3/GPIO6 (in), 47 GND (power), 48 VCC (power)

## CH345T
designator U?
USB to MIDI
footprint SSOP20
pins: 1 RST (in), 2 ACT# (out), 3 MOUT (out), 4 MIN (in), 5 V3 (power), 6 UD+ (io), 7 UD- (io), 8 GND (power), 9 XI (in), 10 XO (out), 11 NC., 12 NC., 13 LEDO (out), 14 LEDI (out), 15 MUX (out), 16 ACK (out), 17 GND (power), 18 NC., 19 VCC (power), 20 NOS# (in)

## CH346C
designator U?
high-speed USB to UART & SPI & Parallel
footprint QFN26C_3X3
pins: 0 GND (power), 1 D7/MISO/RTS1/CFG2/GPIO8 (io), 2 VDD5 (power), 3 GND (power), 4 VDD33 (power), 5 XI (in), 6 XO (io), 7 VDDK (power), 8 UD- (io), 9 UD+ (io), 10 RESET (in), 11 RDNE/RI0/TNOW0/GPIO5 (io), 12 RXD0/ACT/CFG1/RI1/TNOW1/GPIO6 (io), 13 TXD0/SPI_RWS/CFG2/DCD1/GPIO7 (io), 14 VIO (power), 15 CS/DCD0/TX_S/GPIO4 (io), 16 WRNF/CFG0/DTR0/RX_S/GPIO2 (io), 17 A0/DSR0/ACT/GPIO3 (io), 18 RD/RTS0/GPIO0 (io), 19 WR/CTS0/GPIO1 (io), 20 D0/RXD0 (io), 21 D1/TXD0 (io), 22 D2/SPI_RDNE/RXD1 (io), 23 D3/SPI_WRNF/TXD1 (io), 24 D4/SCS/DSR1/GPIO11 (io), 25 D5/SCK/CTS1/GPIO9 (io), 26 D6/MOSI/DTR1/CFG1/GPIO10 (io)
